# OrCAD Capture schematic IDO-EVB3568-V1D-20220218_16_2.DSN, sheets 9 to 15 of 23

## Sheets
9 P11. VO-HDMI2.0 TX: size A4; note: VO-HDMI2.0 TX
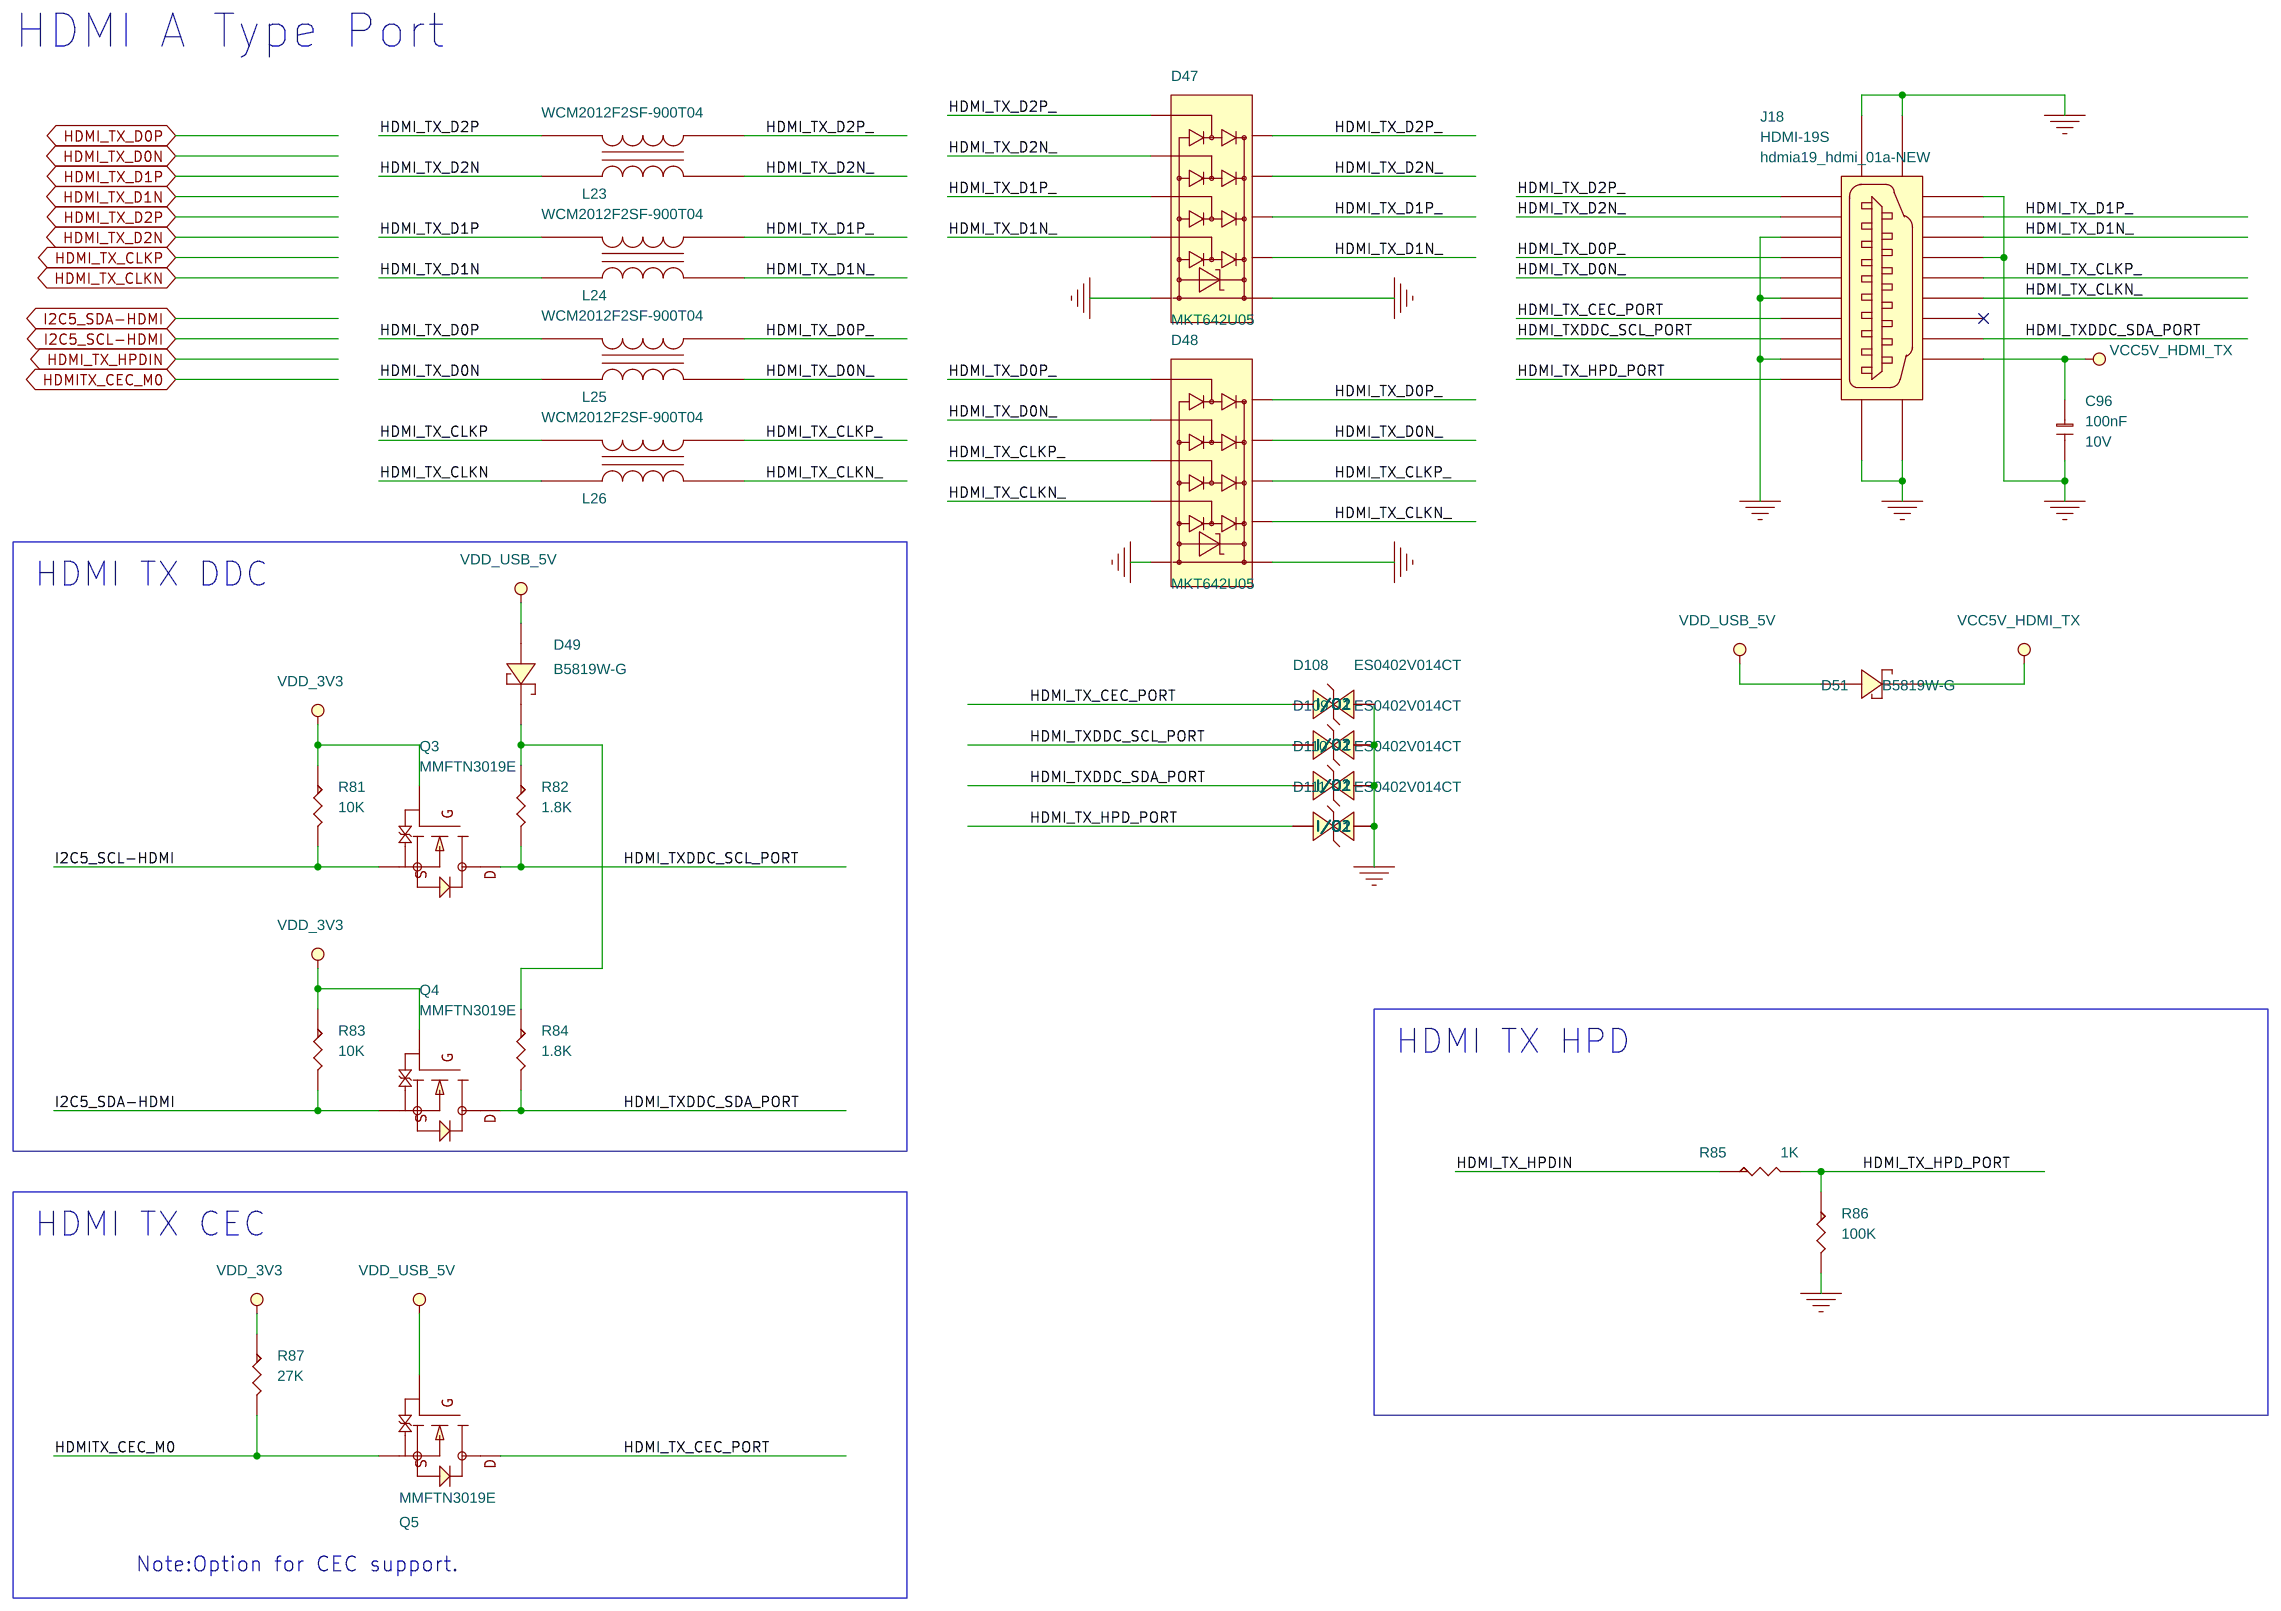
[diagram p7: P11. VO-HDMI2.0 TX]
10 P12. VO-LCM_eDP TX: size A4; note: VO-LCM_eDP TX
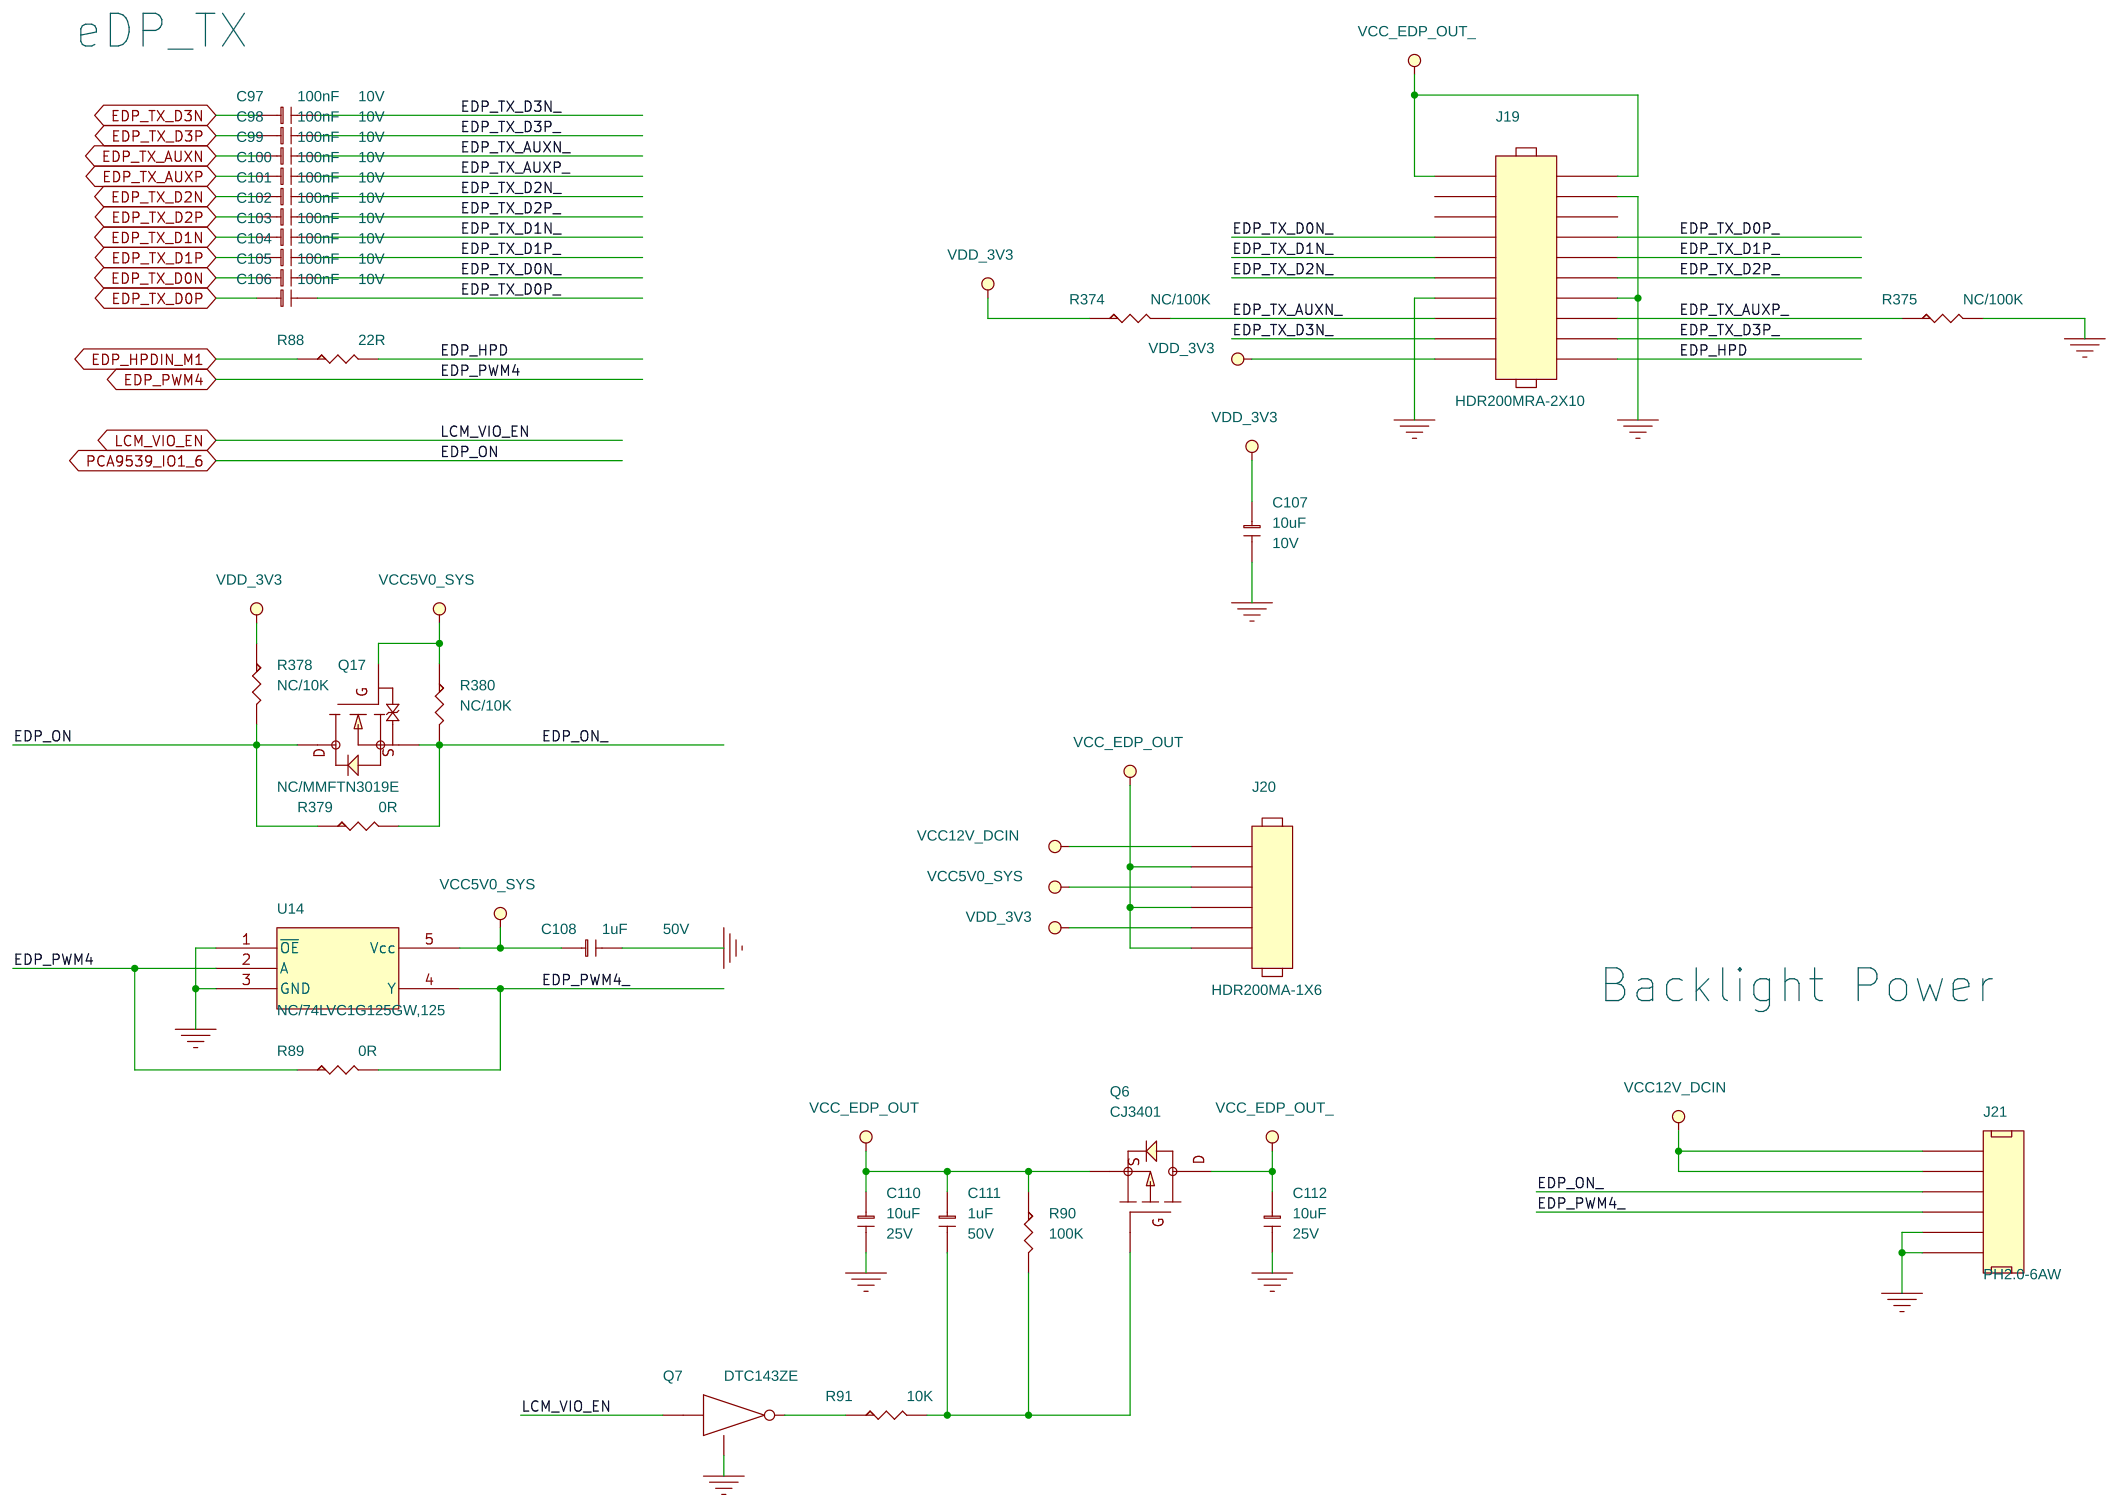
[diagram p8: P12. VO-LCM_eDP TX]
11 P13. VO-LCM_MIPI_DSI_TX0: size A4; note: VO-LCM_MIPI_DSI_TX0
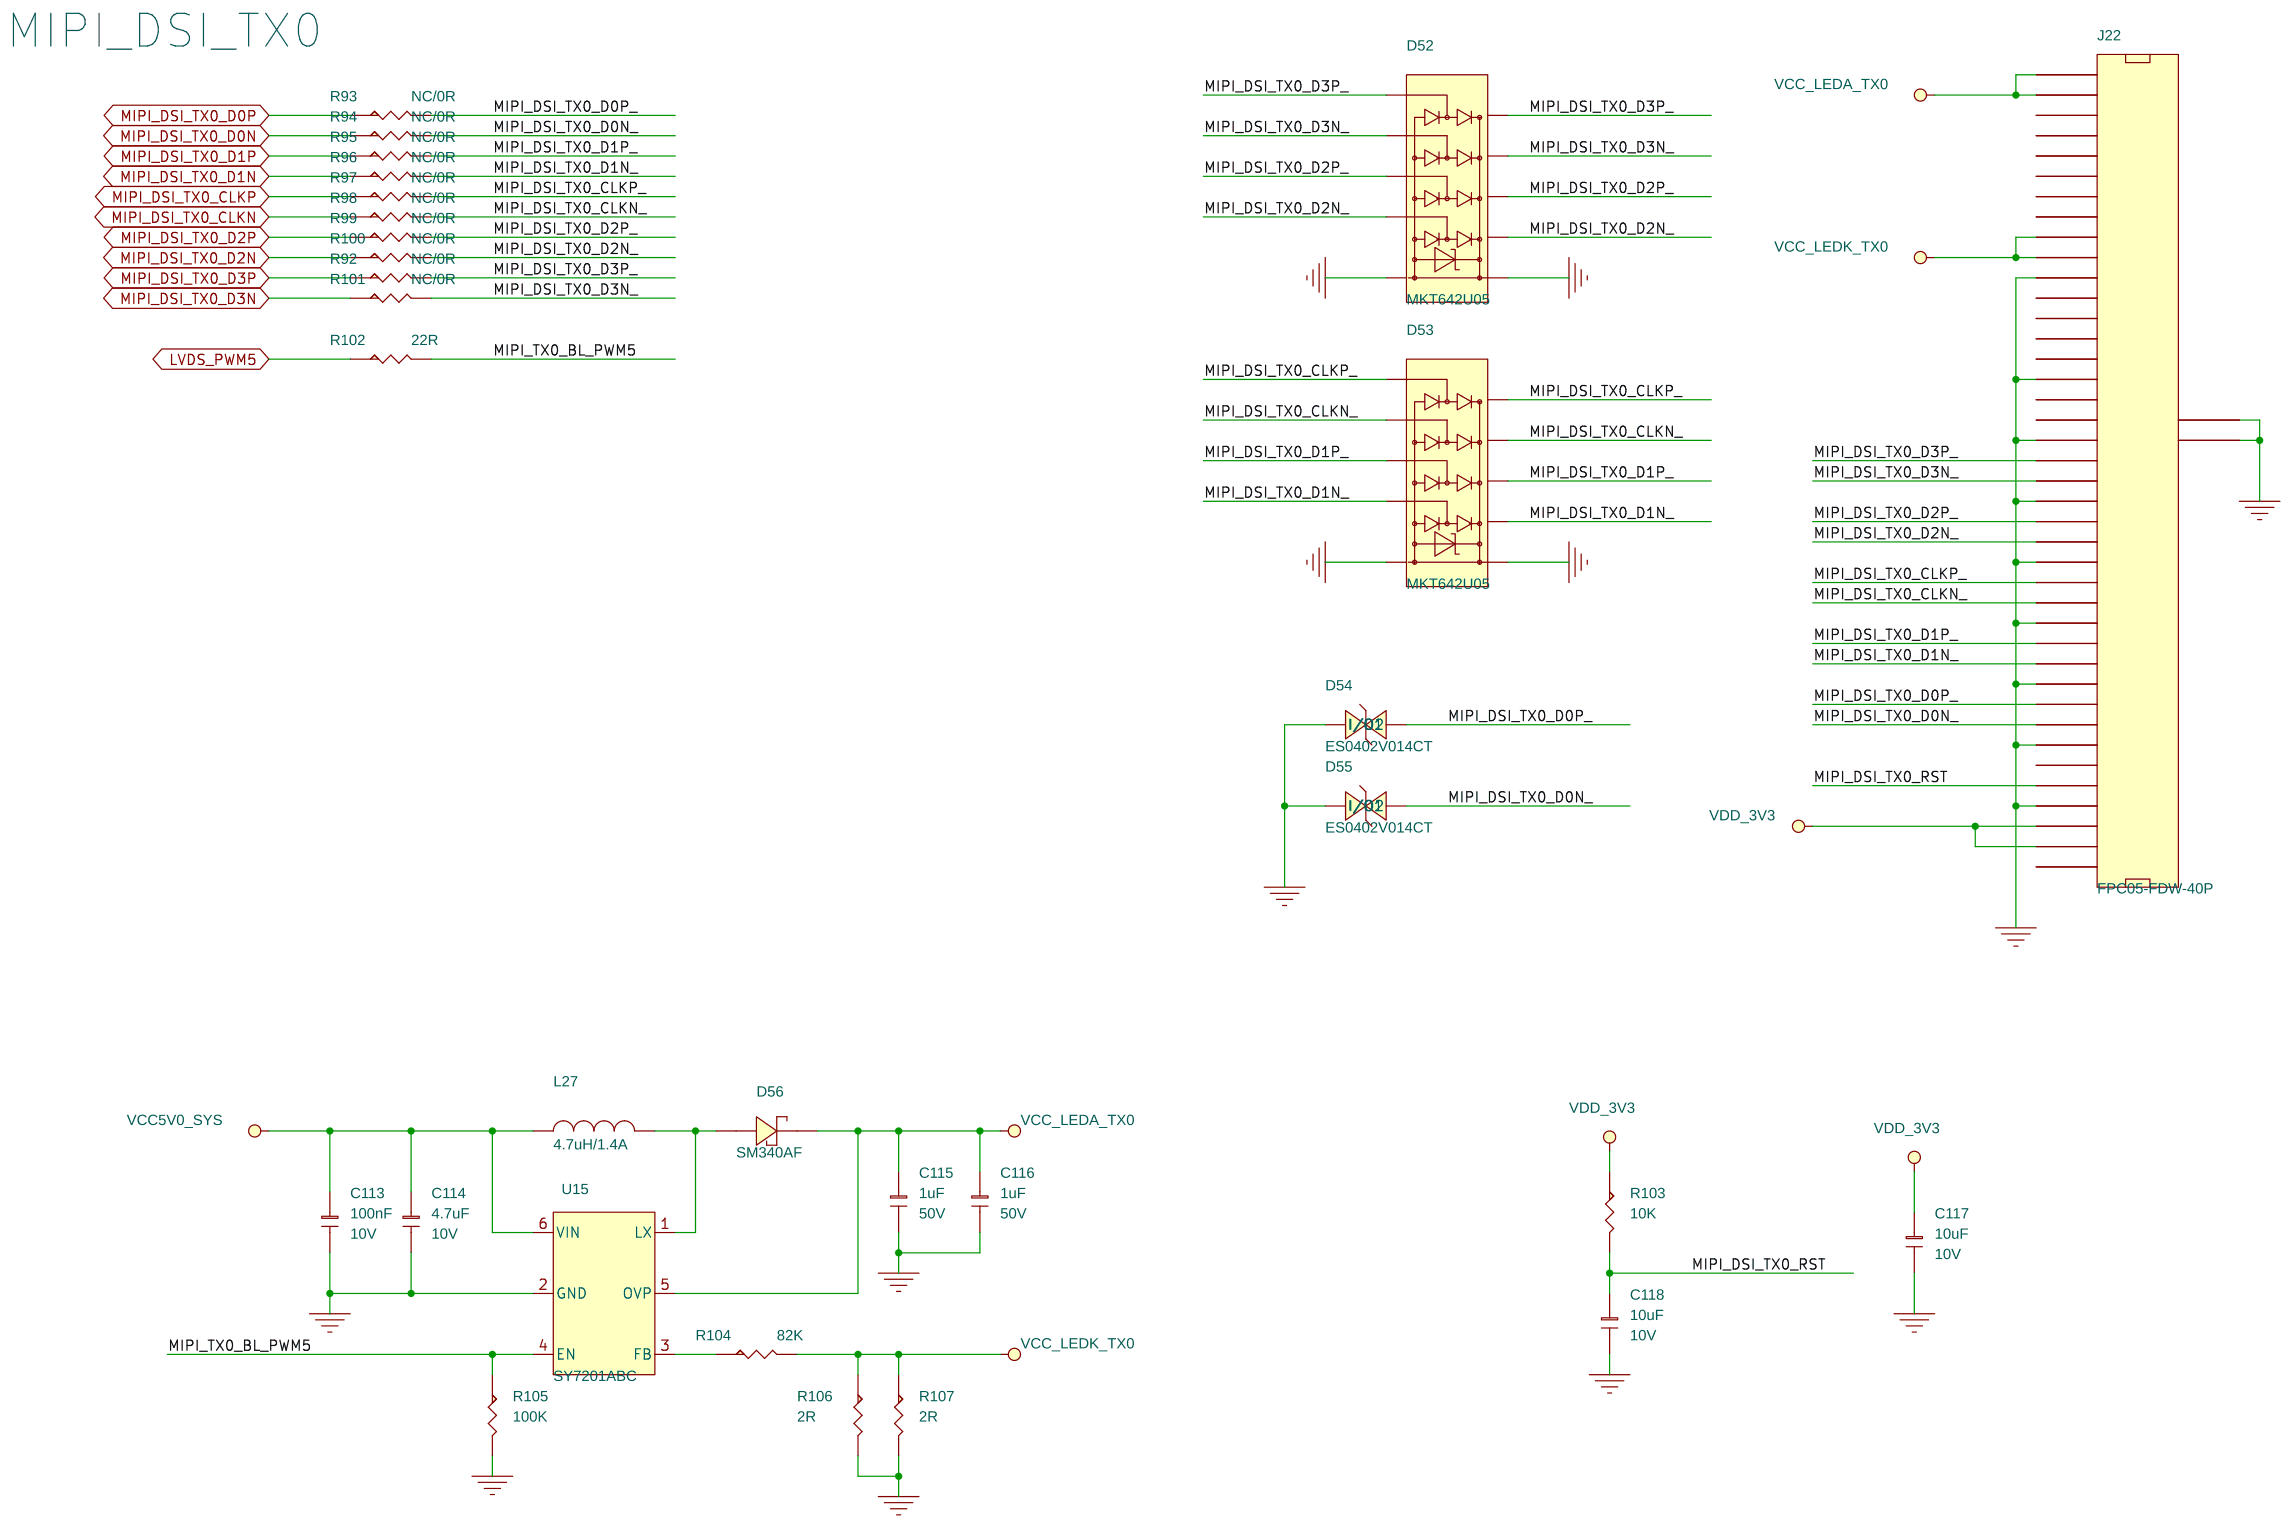
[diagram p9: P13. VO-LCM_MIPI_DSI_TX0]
12 P14. VO-LCM_MIPI_DSI_TX1: size A4; note: VO-LCM_MIPI_DSI_TX1
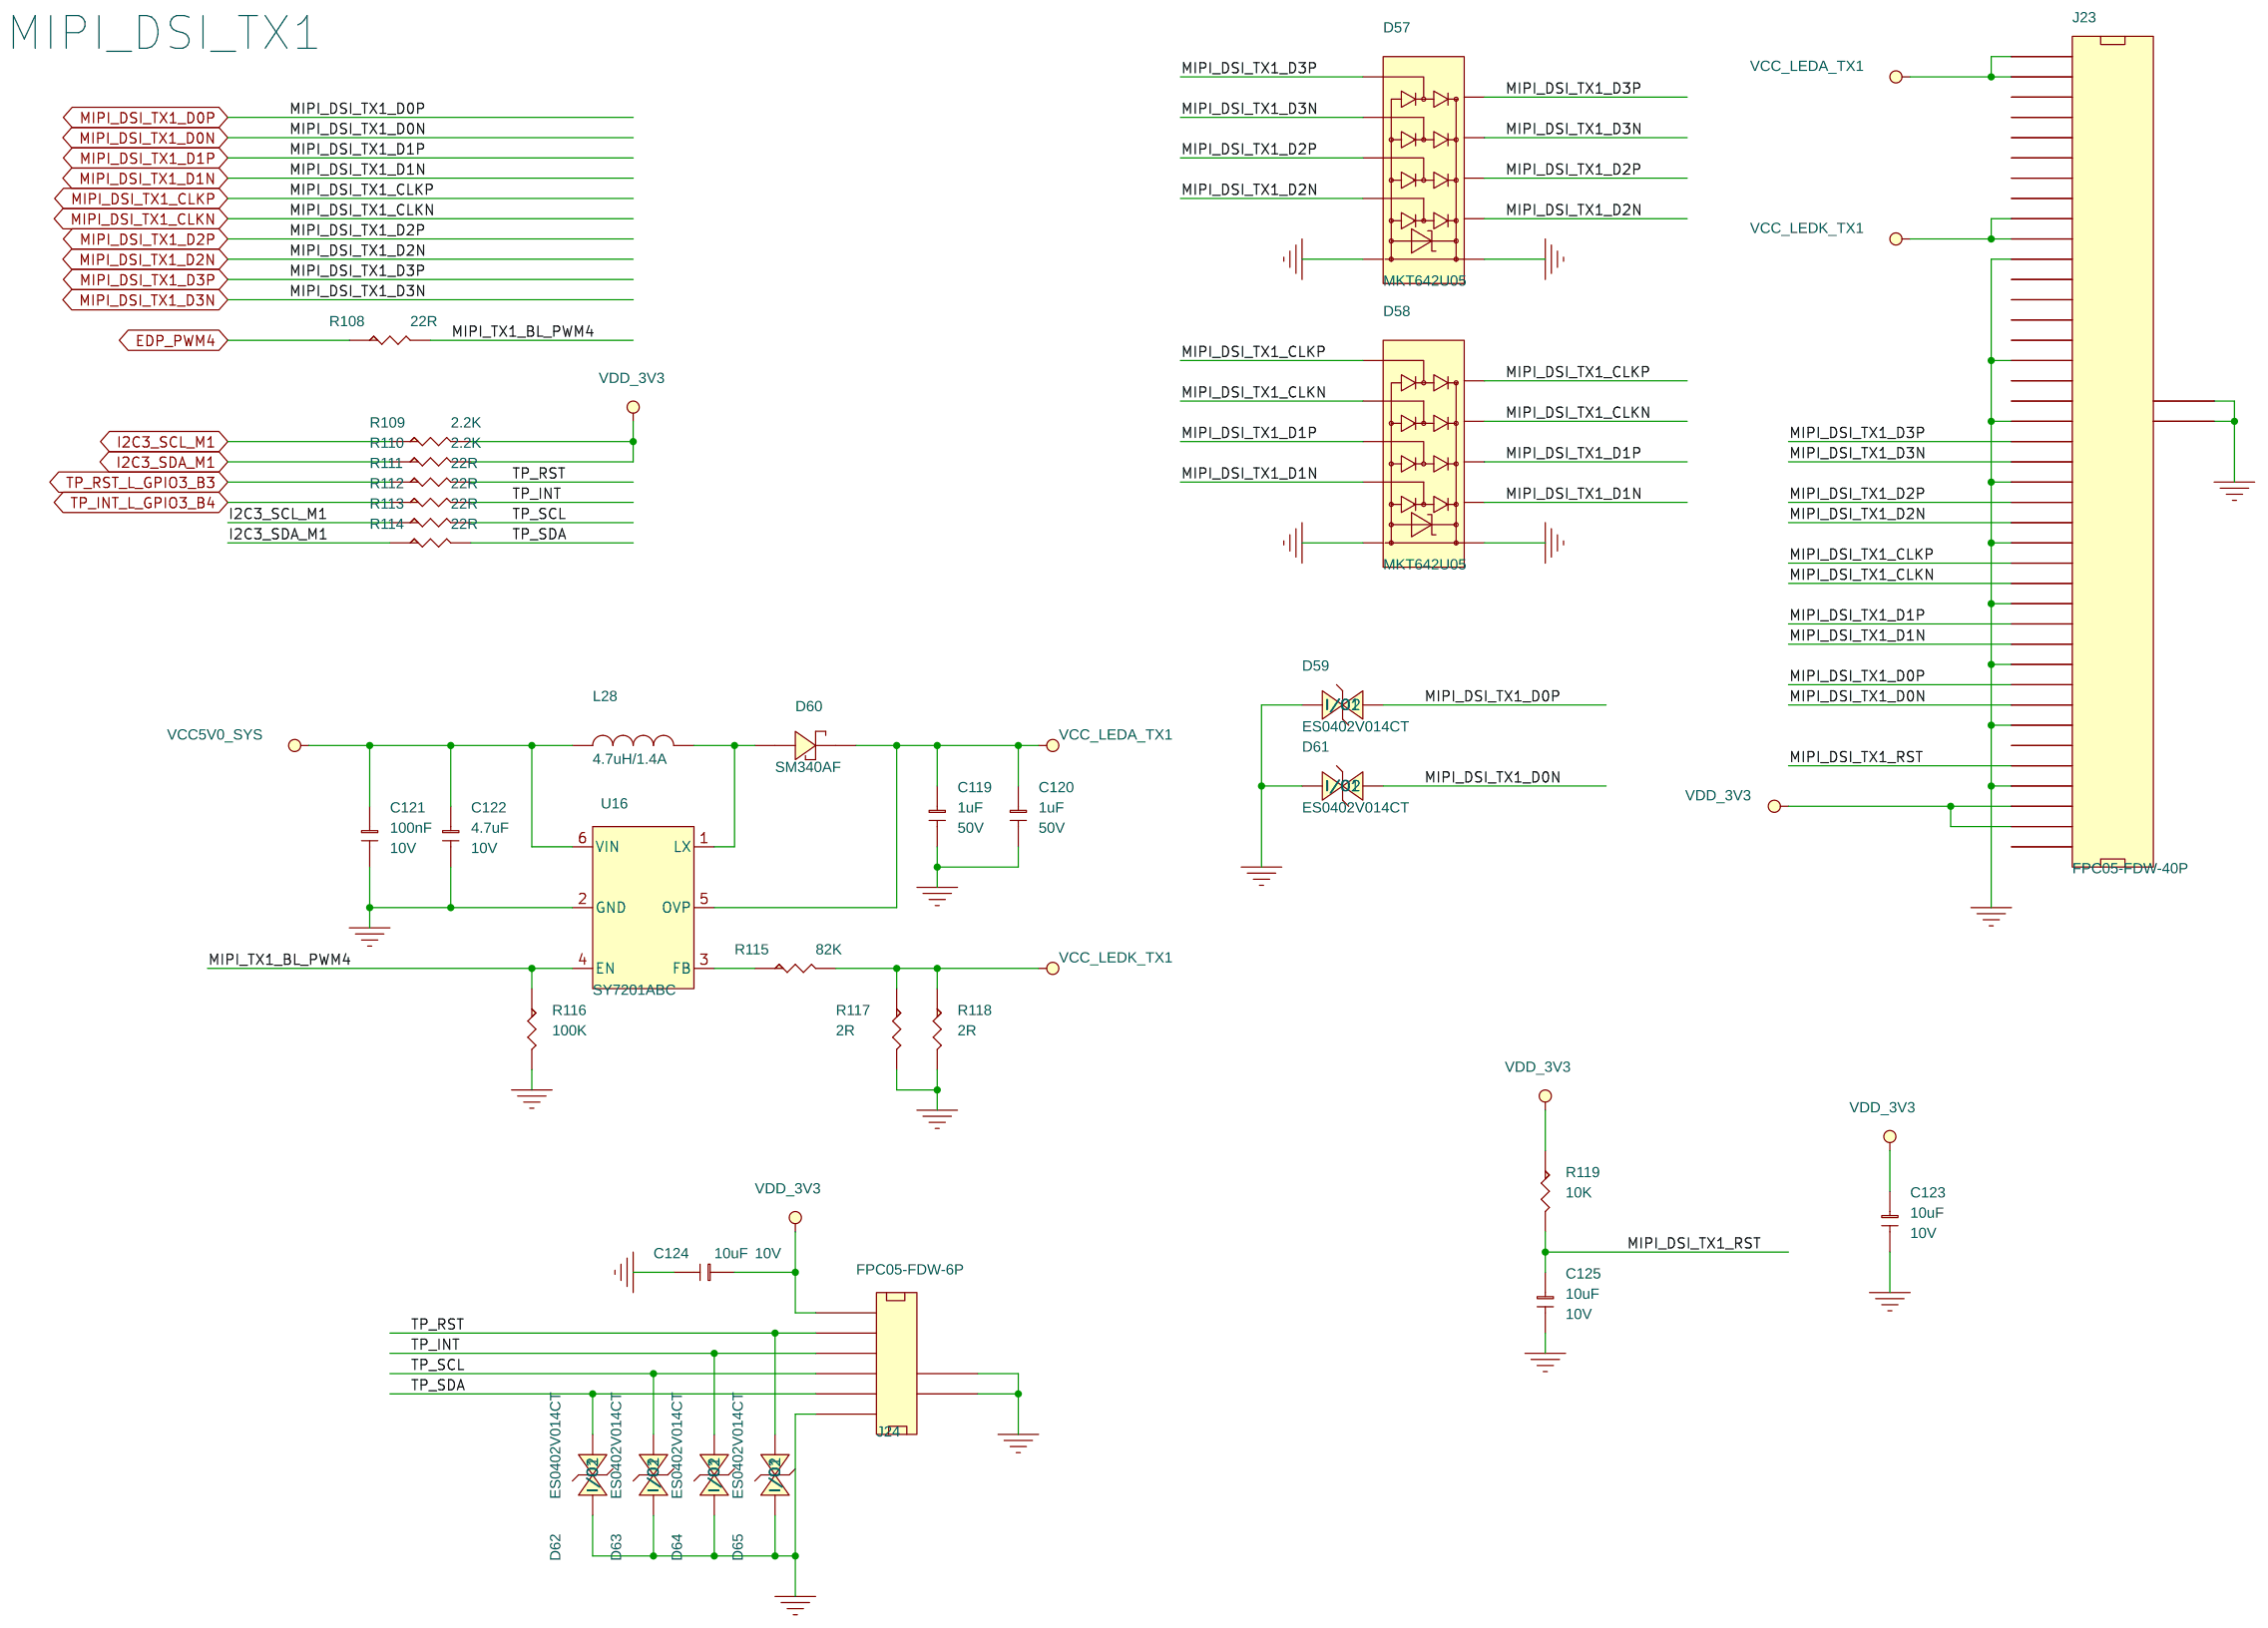
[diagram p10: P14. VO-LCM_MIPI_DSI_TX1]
13 P15. VO-GM8775C-LVDS: size A3; note: VO-GM8775C-LVDS
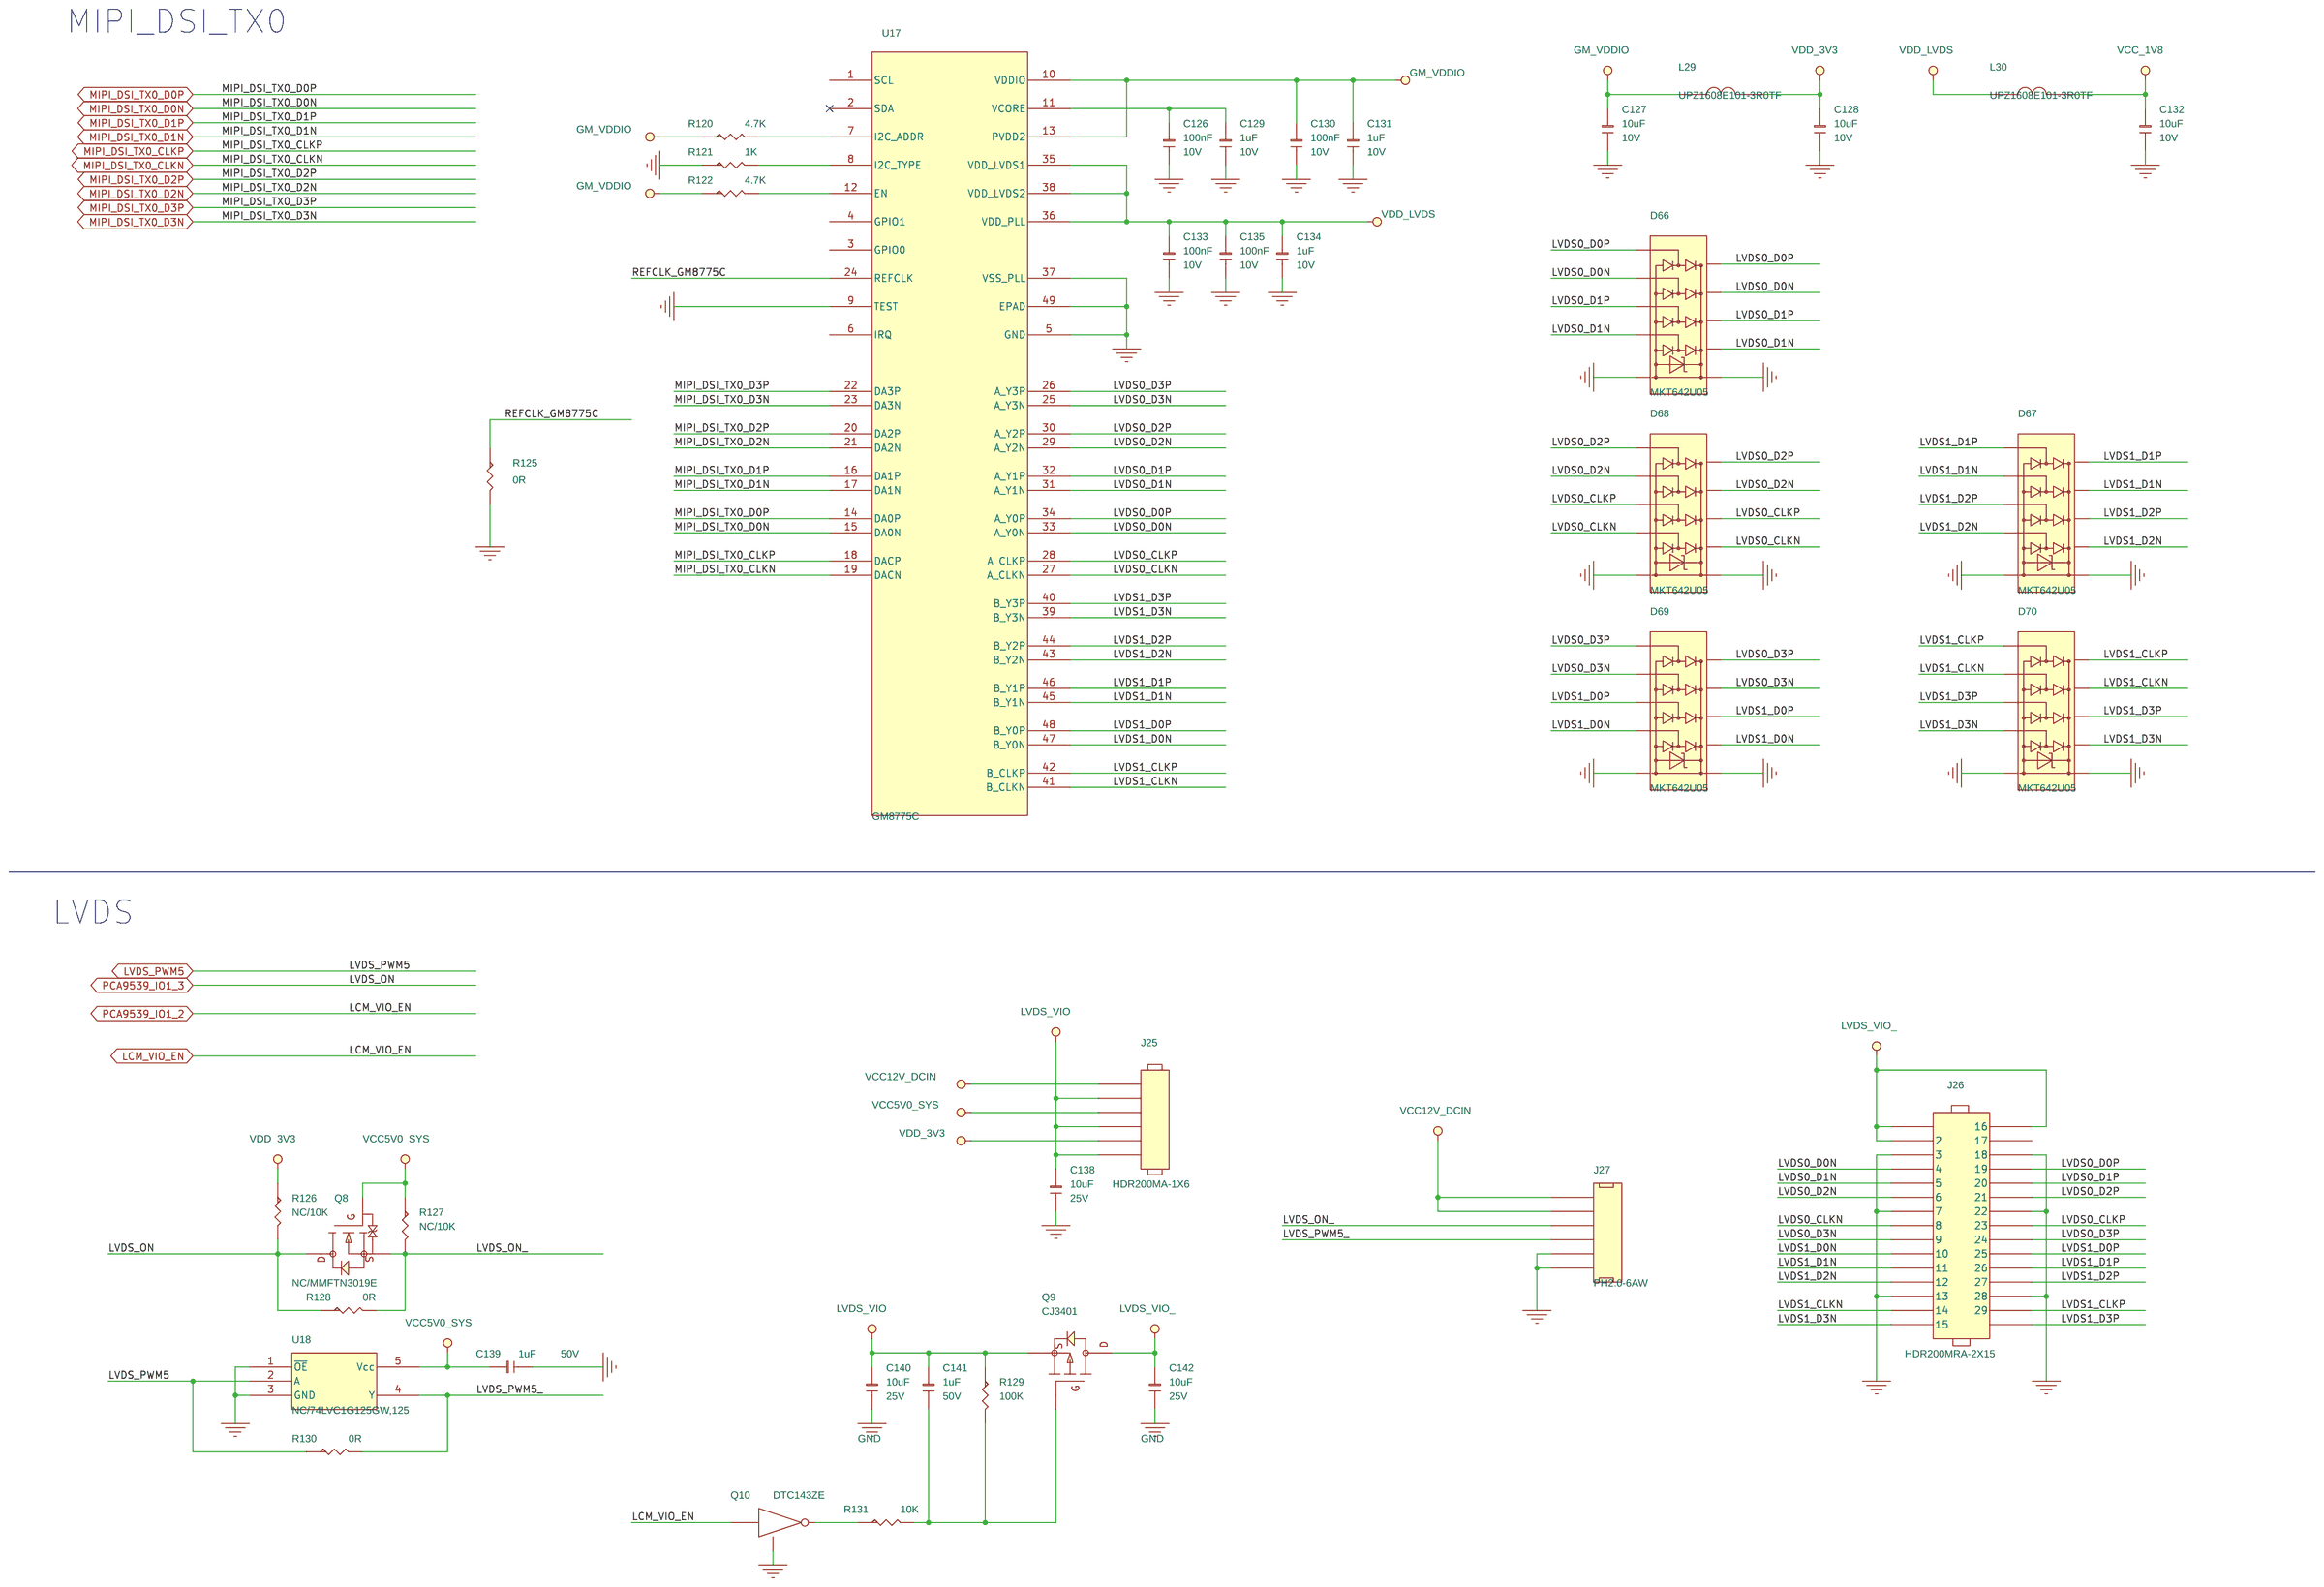
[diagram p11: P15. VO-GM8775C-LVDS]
14 P16. VI-OV5648: size A4; note: VI-OV5648
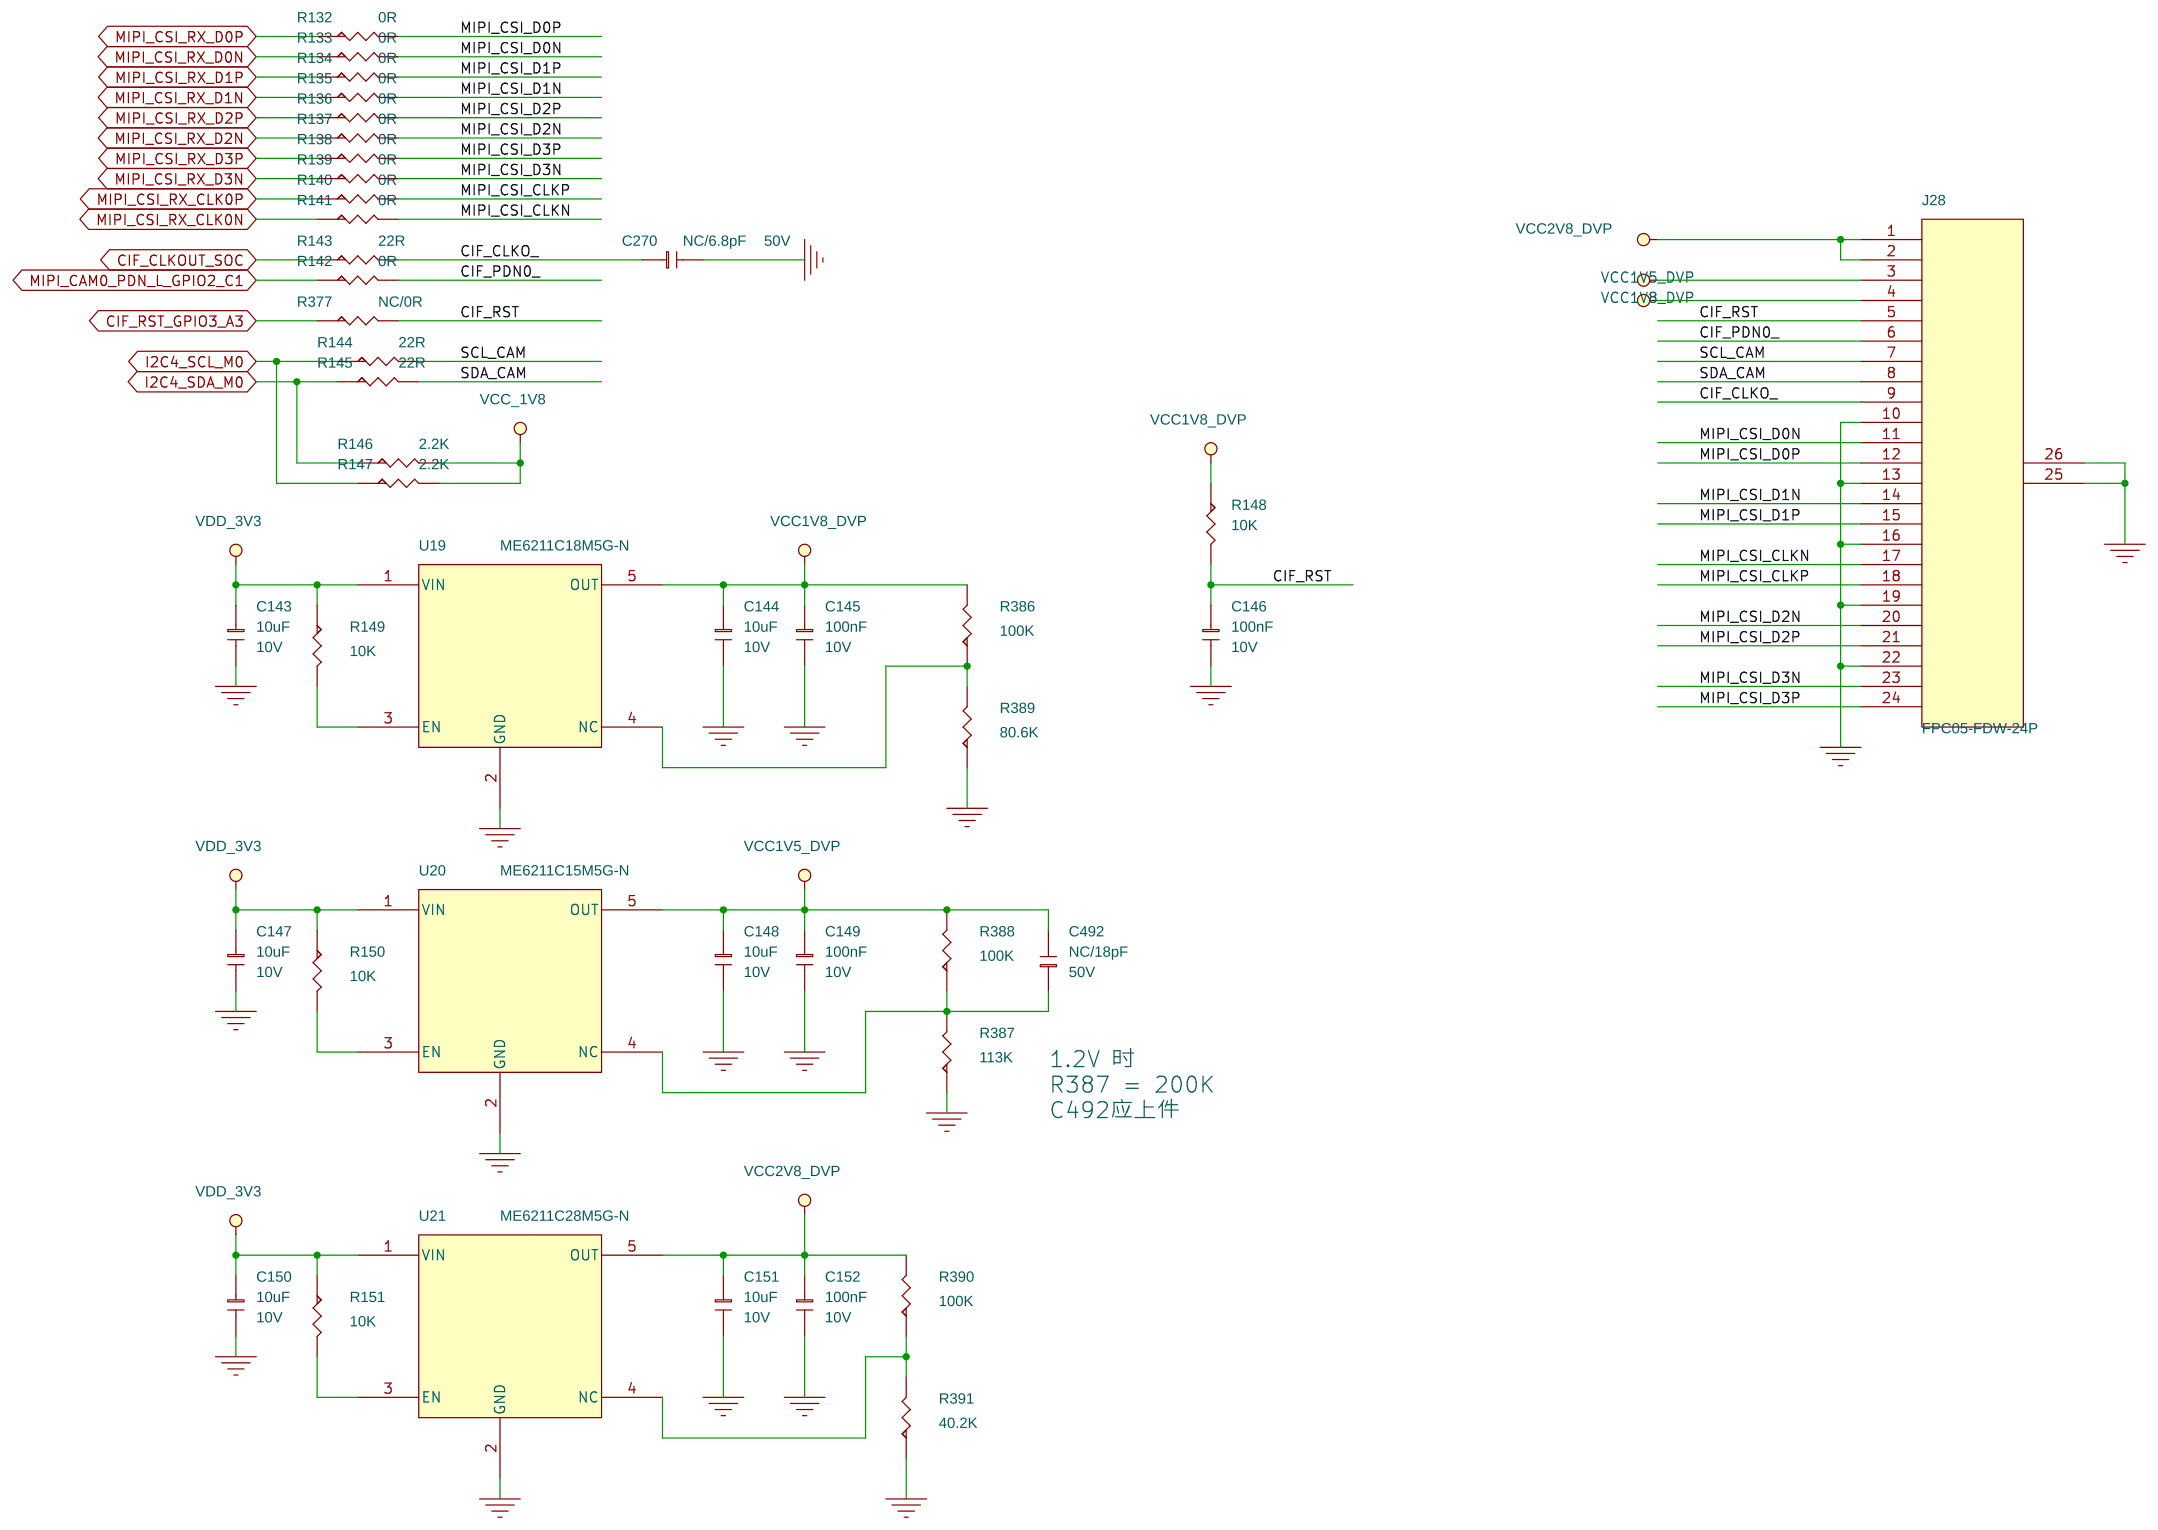
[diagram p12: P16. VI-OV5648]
15 P18. Ethernet-GEPHY_RGMII0: size A2; note: Ethernet-GEPHY_RGMII0
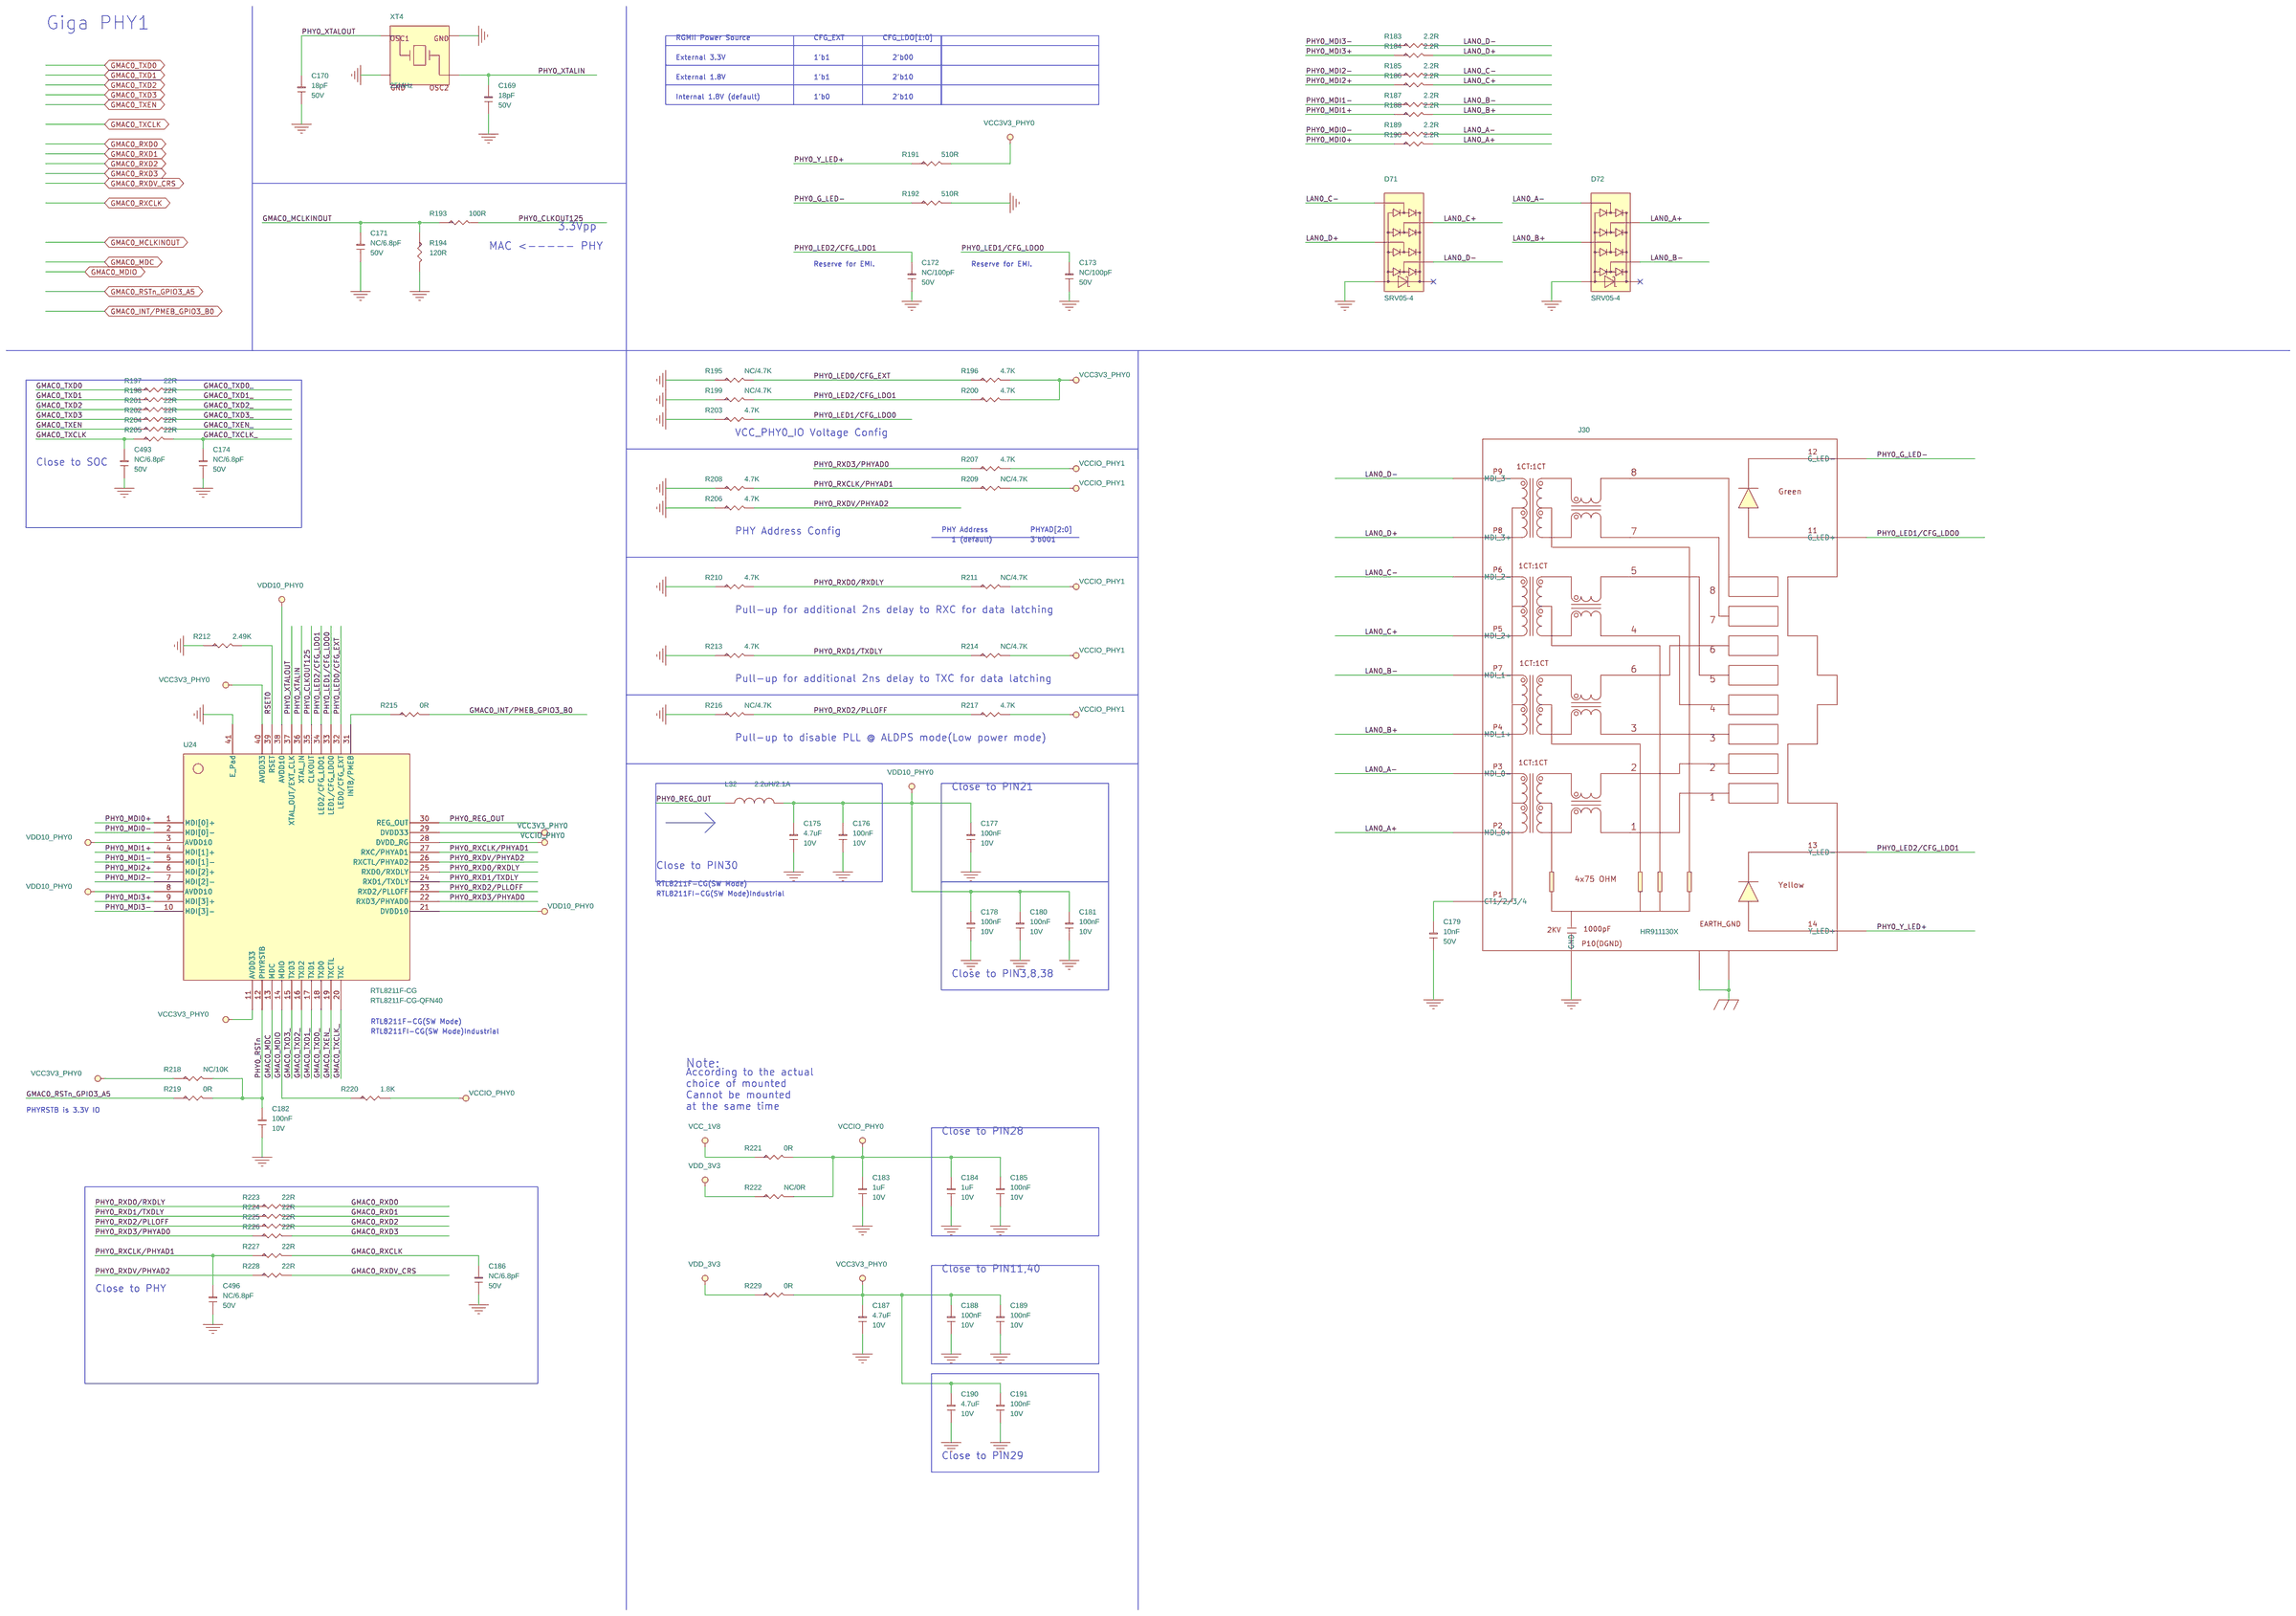
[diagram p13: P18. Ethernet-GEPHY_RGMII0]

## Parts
sheet P11. VO-HDMI2.0 TX
C96  100nF  [C0402L]
D47  MKT642U05  [ESD-DFN2510A-10]
D48  MKT642U05  [ESD-DFN2510A-10]
D49  B5819W-G  [SOD123]
D51  B5819W-G  [SOD123]
D108  ES0402V014CT  [V0402]
D109  ES0402V014CT  [V0402]
D110  ES0402V014CT  [V0402]
D111  ES0402V014CT  [V0402]
J18  HDMI-19S  [hdmia19_hdmi_01a-NEW]
L23  WCM2012F2SF-900T04  [CMLS-ACM2012]
L24  WCM2012F2SF-900T04  [CMLS-ACM2012]
L25  WCM2012F2SF-900T04  [CMLS-ACM2012]
L26  WCM2012F2SF-900T04  [CMLS-ACM2012]
Q3  MMFTN3019E  [SOT523]
Q4  MMFTN3019E  [SOT523]
Q5  MMFTN3019E  [SOT523]
R81  10K  [R0402L]
R82  1.8K  [R0402L]
R83  10K  [R0402L]
R84  1.8K  [R0402L]
R85  1K  [R0402L]
R86  100K  [R0402L]
R87  27K  [R0402L]
sheet P12. VO-LCM_eDP TX
C97  100nF  [C0402L]
C98  100nF  [C0402L]
C99  100nF  [C0402L]
C100  100nF  [C0402L]
C101  100nF  [C0402L]
C102  100nF  [C0402L]
C103  100nF  [C0402L]
C104  100nF  [C0402L]
C105  100nF  [C0402L]
C106  100nF  [C0402L]
C107  10uF  [C0603L]
C108  1uF  [C0603L]
C110  10uF  [C0805L]
C111  1uF  [C0603L]
C112  10uF  [C0805L]
J19  HDR200MRA-2X10  [HDR200MRA-2X10]
J20  HDR200MA-1X6  [HDR200MA-1X6]
J21  PH2.0-6AW  [PH200-6AW]
Q6  CJ3401  [SOT23]
Q7  DTC143ZE  [SOT523]
Q17  NC/MMFTN3019E  [SOT523]
R88  22R  [R0402L]
R89  0R  [R0402L]
R90  100K  [R0402L]
R91  10K  [R0402L]
R374  NC/100K  [R0402L]
R375  NC/100K  [R0402L]
R378  NC/10K  [R0402L]
R379  0R  [R0402L]
R380  NC/10K  [R0402L]
U14  NC/74LVC1G125GW,125  [SOT353]
sheet P13. VO-LCM_MIPI_DSI_TX0
C113  100nF  [C0402L]
C114  4.7uF  [C0402L]
C115  1uF  [C0603L]
C116  1uF  [C0603L]
C117  10uF  [C0603L]
C118  10uF  [C0603L]
D52  MKT642U05  [ESD-DFN2510A-10]
D53  MKT642U05  [ESD-DFN2510A-10]
D54  ES0402V014CT  [V0402]
D55  ES0402V014CT  [V0402]
D56  SM340AF  [SMAF]
J22  FPC05-FDW-40P  [FPC05-FDW-40P]
L27  4.7uH/1.4A  [L2520]
R92  NC/0R  [R0402L]
R93  NC/0R  [R0402L]
R94  NC/0R  [R0402L]
R95  NC/0R  [R0402L]
R96  NC/0R  [R0402L]
R97  NC/0R  [R0402L]
R98  NC/0R  [R0402L]
R99  NC/0R  [R0402L]
R100  NC/0R  [R0402L]
R101  NC/0R  [R0402L]
R102  22R  [R0402L]
R103  10K  [R0402L]
R104  82K  [R0402L]
R105  100K  [R0402L]
R106  2R  [R0805L]
R107  2R  [R0805L]
U15  SY7201ABC  [SOT23-6]
sheet P14. VO-LCM_MIPI_DSI_TX1
C119  1uF  [C0603L]
C120  1uF  [C0603L]
C121  100nF  [C0402L]
C122  4.7uF  [C0402L]
C123  10uF  [C0603L]
C124  10uF  [C0603L]
C125  10uF  [C0603L]
D57  MKT642U05  [ESD-DFN2510A-10]
D58  MKT642U05  [ESD-DFN2510A-10]
D59  ES0402V014CT  [V0402]
D60  SM340AF  [SMAF]
D61  ES0402V014CT  [V0402]
D62  ES0402V014CT  [V0402]
D63  ES0402V014CT  [V0402]
D64  ES0402V014CT  [V0402]
D65  ES0402V014CT  [V0402]
J23  FPC05-FDW-40P  [FPC05-FDW-40P]
J24  FPC05-FDW-6P  [FPC05-FDW-6P]
L28  4.7uH/1.4A  [L2520]
R108  22R  [R0402L]
R109  2.2K  [R0402L]
R110  2.2K  [R0402L]
R111  22R  [R0402L]
R112  22R  [R0402L]
R113  22R  [R0402L]
R114  22R  [R0402L]
R115  82K  [R0402L]
R116  100K  [R0402L]
R117  2R  [R0805L]
R118  2R  [R0805L]
R119  10K  [R0402L]
U16  SY7201ABC  [SOT23-6]
sheet P15. VO-GM8775C-LVDS
C126  100nF  [C0402L]
C127  10uF  [C0603L]
C128  10uF  [C0603L]
C129  1uF  [C0402L]
C130  100nF  [C0402L]
C131  1uF  [C0402L]
C132  10uF  [C0603L]
C133  100nF  [C0402L]
C134  1uF  [C0402L]
C135  100nF  [C0402L]
C138  10uF  [C0805L]
C139  1uF  [C0603L]
C140  10uF  [C0805L]
C141  1uF  [C0603L]
C142  10uF  [C0805L]
D66  MKT642U05  [ESD-DFN2510A-10]
D67  MKT642U05  [ESD-DFN2510A-10]
D68  MKT642U05  [ESD-DFN2510A-10]
D69  MKT642U05  [ESD-DFN2510A-10]
D70  MKT642U05  [ESD-DFN2510A-10]
J25  HDR200MA-1X6  [HDR200MA-1X6]
J26  HDR200MRA-2X15  [HDR200MRA-2X15]
J27  PH2.0-6AW  [PH200-6AW]
L29  UPZ1608E101-3R0TF  [L0603]
L30  UPZ1608E101-3R0TF  [L0603]
Q8  NC/MMFTN3019E  [SOT523]
Q9  CJ3401  [SOT23]
Q10  DTC143ZE  [SOT523]
R120  4.7K  [R0402L]
R121  1K  [R0402L]
R122  4.7K  [R0402L]
R125  0R  [R0402L]
R126  NC/10K  [R0402L]
R127  NC/10K  [R0402L]
R128  0R  [R0402L]
R129  100K  [R0402L]
R130  0R  [R0402L]
R131  10K  [R0402L]
U17  GM8775C  [qfn50p700x700x100-49an]
U18  NC/74LVC1G125GW,125  [SOT353]
sheet P16. VI-OV5648
C143  10uF  [C0603L]
C144  10uF  [C0603L]
C145  100nF  [C0402L]
C146  100nF  [C0402L]
C147  10uF  [C0603L]
C148  10uF  [C0603L]
C149  100nF  [C0402L]
C150  10uF  [C0603L]
C151  10uF  [C0603L]
C152  100nF  [C0402L]
C270  NC/6.8pF  [C0402L]
C492  NC/18pF  [C0402L]
J28  FPC05-FDW-24P  [FPC05-ZDW-24P]
R132  0R  [R0402L]
R133  0R  [R0402L]
R134  0R  [R0402L]
R135  0R  [R0402L]
R136  0R  [R0402L]
R137  0R  [R0402L]
R138  0R  [R0402L]
R139  0R  [R0402L]
R140  0R  [R0402L]
R141  0R  [R0402L]
R142  0R  [R0402L]
R143  22R  [R0402L]
R144  22R  [R0402L]
R145  22R  [R0402L]
R146  2.2K  [R0402L]
R147  2.2K  [R0402L]
R148  10K  [R0402L]
R149  10K  [R0402L]
R150  10K  [R0402L]
R151  10K  [R0402L]
R377  NC/0R  [R0402L]
R386  100K  [R0402L]
R387  113K  [R0402L]
R388  100K  [R0402L]
R389  80.6K  [R0402L]
R390  100K  [R0402L]
R391  40.2K  [R0402L]
U19  ME6211C18M5G-N  [SOT23-5]
U20  ME6211C15M5G-N  [SOT23-5]
U21  ME6211C28M5G-N  [SOT23-5]
sheet P18. Ethernet-GEPHY_RGMII0
C169  18pF  [C0402L]
C170  18pF  [C0402L]
C171  NC/6.8pF  [C0402L]
C172  NC/100pF  [C0402L]
C173  NC/100pF  [C0402L]
C174  NC/6.8pF  [C0402L]
C175  4.7uF  [C0402L]
C176  100nF  [C0402L]
C177  100nF  [C0402L]
C178  100nF  [C0402L]
C179  10nF  [C0402L]
C180  100nF  [C0402L]
C181  100nF  [C0402L]
C182  100nF  [C0402L]
C183  1uF  [C0402L]
C184  1uF  [C0402L]
C185  100nF  [C0402L]
C186  NC/6.8pF  [C0402L]
C187  4.7uF  [C0402L]
C188  100nF  [C0402L]
C189  100nF  [C0402L]
C190  4.7uF  [C0402L]
C191  100nF  [C0402L]
C493  NC/6.8pF  [C0402L]
C496  NC/6.8pF  [C0402L]
D71  SRV05-4  [SOT23-6]
D72  SRV05-4  [SOT23-6]
J30  HR911130X  [HR911130X]
L32  2.2uH/2.1A  [L2520]
R183  2.2R  [R0402L]
R184  2.2R  [R0402L]
R185  2.2R  [R0402L]
R186  2.2R  [R0402L]
R187  2.2R  [R0402L]
R188  2.2R  [R0402L]
R189  2.2R  [R0402L]
R190  2.2R  [R0402L]
R191  510R  [R0402L]
R192  510R  [R0402L]
R193  100R  [R0402L]
R194  120R  [R0402L]
R195  NC/4.7K  [R0402L]
R196  4.7K  [R0402L]
R197  22R  [R0402L]
R198  22R  [R0402L]
R199  NC/4.7K  [R0402L]
R200  4.7K  [R0402L]
R201  22R  [R0402L]
R202  22R  [R0402L]
R203  4.7K  [R0402L]
R204  22R  [R0402L]
R205  22R  [R0402L]
R206  4.7K  [R0402L]
R207  4.7K  [R0402L]
R208  4.7K  [R0402L]
R209  NC/4.7K  [R0402L]
R210  4.7K  [R0402L]
R211  NC/4.7K  [R0402L]
R212  2.49K  [R0402L]
R213  4.7K  [R0402L]
R214  NC/4.7K  [R0402L]
R215  0R  [R0402L]
R216  NC/4.7K  [R0402L]
R217  4.7K  [R0402L]
R218  NC/10K  [R0402L]
R219  0R  [R0402L]
R220  1.8K  [R0402L]
R221  0R  [R0402L]
R222  NC/0R  [R0402L]
R223  22R  [R0402L]
R224  22R  [R0402L]
R225  22R  [R0402L]
R226  22R  [R0402L]
R227  22R  [R0402L]
R228  22R  [R0402L]
R229  0R  [R0402L]
U24  RTL8211F-CG  [RTL8211F-CG-QFN40]
XT4  25MHz  [xtal_32x25_4p]

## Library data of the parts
C96-C106 C113 C121 C126 C130 C133 C135 C145 C146 C149 C152 C176-C178 C180-C182 C185 C188 C189 C191 = C-0402: DSC1: ±10%; DSC2: 10V; DSC3: X7R; ID: 60; Manufacture: 三星|国巨|村田; Part Name: 贴片电容; Part Number: C020102120060; Price: 0.01
D47 D48 D52 D53 D57 D58 D66-D70 = DI-ESD-MKT642U05: DSC2: Vdc=5V; DSC3: Vbr=6V; DSC4: Vc=16V; DSC5: Cj=0.35pF; ID: 8; Manufacture: 米客方德; Part Name: ESD; Part Number: C040502250008; Price: 0.15; Solder: 推荐
D49 D51 = DI-XI-S: DSC1: VR=40V; DSC2: IF=1A; DSC3: VF=600mV/1A; DSC4: IR=1mA; ID: 5; Manufacture: 长电; Part Name: 肖特基二级管; Part Number: C040202220005; Price: 0.13
D54 D55 D59 D61-D65 D108-D111 = DI-ESD: DSC1: 双向; DSC2: Vdc=14V; DSC3: Vbr=300V; DSC4: Vc=30V; DSC5: Cj=0.25pF; ERP Number: 1010800023; ID: 2; Manufacture: AEM; Part Name: ESD; Part Number: C040502250002; Price: 0.06
J18 = J-HDMI-19P: DSC1: HDMI 19P母座SMT铜壳四脚 黑胶LCP 耐高温; DSC2: 15*11.8*6mm; DSC3: 贴片; ID: 7; Part Name: HDMI座; Part Number: J050302920001
L23-L26 = L-CMLS-ACM2012: DSC1: 90uH@100kHz; DSC2: 90Ω@100MHz; DSC3: 400mA; DSC4: DCR=300mΩ; DSC5: -40℃ ~ +125℃; DSC6: SMD_4P,2x1.2mm; ERP Number: 1010200196; ID: 1; Manufacture: 台庆; Part Name: 信号共模电感; Part Number: C060402360001; Price: 0.13
Q3-Q5 Q8 Q17 = N-MOS-Q: DSC1: Vds=30V; DSC2: Id=100mA; DSC3: Vgs(th)=1.5V; DSC4: Vgs=±20V; DSC5: pd=150mW; ERP Number: 1010800011; ID: 4; Manufacture: 先科; Part Name: N-MOS; Part Number: C030202190004; Price: 0.1
R81 R83 R91 R103 R119 R126 R127 R131 R148-R151 R218 R378 R380 = R-0402: DSC1: ±1%; DSC2: 1/16W; ERP Number: 1010200140; ID: 856; Part Name: 贴片电阻; Part Number: C011002080856; Price: 0.01
R82 R84 R220 = R-0402: DSC1: ±1%; DSC2: 1/16W; ID: 769; Part Name: 贴片电阻; Part Number: C011002080769; Price: 0.01
R85 R121 = R-0402: DSC1: ±1%; DSC2: 1/16W; ERP Number: 1010200113; ID: 742; Part Name: 贴片电阻; Part Number: C011002080742; Price: 0.01
R86 R90 R105 R116 R129 R374 R375 = R-0402: DSC1: ±1%; DSC2: 1/16W; ERP Number: 1010200137; ID: 976; Part Name: 贴片电阻; Part Number: C011002080976; Price: 0.01
R87 = R-0402: DSC1: ±1%; DSC2: 1/16W; ID: 904; Part Name: 贴片电阻; Part Number: C011002080904; Price: 0.01
C107 C117 C118 C123-C125 C127 C128 C132 C143 C144 C147 C148 C150 C151 = C-0603: DSC1: ±20%; DSC2: 10V; DSC3: X5R; ERP Number: 1010200076; ID: 71; Manufacture: 三星|国巨|村田; Part Name: 贴片电容; Part Number: C020102120071; Price: 0.05
C108 C111 C115 C116 C119 C120 C139 C141 = C-0603: DSC1: ±10%; DSC2: 50V; DSC3: X5R; ERP Number: 1010200142; ID: 69; Manufacture: 三星|国巨|村田; Part Name: 贴片电容; Part Number: C020102120069; Price: 0.04
C110 C112 C138 C140 C142 = C-0805: DSC1: ±10%; DSC2: 25V; DSC3: X5R; ERP Number: 1010200144; ID: 74; Manufacture: 三星|国巨|村田; Part Name: 贴片电容; Part Number: C020102120074; Price: 0.09
J19 = J-HDR-D-20: DSC1: 双排单塑; DSC2: 2x10; DSC3: 2mm脚距; DSC4: 通孔弯针; DSC5: 2.8+2(H塑高)+4 mm; DSC6: 黑胶; DSC7: A2005WR-2x10P（CJT); ID: 29; Part Name: 双排针; Part Number: J010102760085
J20 J25 = J-HDR-6: DSC1: 单排单塑; DSC2: 1x6; DSC3: 2mm脚距; DSC4: 通孔直针; DSC5: 针长8.8mm  2.8+2(H塑高)+4 mm; DSC6: 黑胶; ID: 66; Part Name: 单排针; Part Number: J010206123880
J21 J27 = J-H-6P: DSC1: 6p; DSC2: 2.0mm间距; DSC3: 通孔90度弯针; DSC4: 米黄色胶壳 耐高温; DSC5: A2001WR-6P(CJT); ID: 20; Part Name: PH; Part Number: J020302820024
Q6 Q9 = P-MOS: DSC1: Vds=-30V; DSC2: Id=-4.2A; DSC3: Vgs(th)=1.3V; DSC4: Vgs=±12V; DSC5: pd=350mW; ERP Number: 1010800001; ID: 1; Manufacture: 长电; Part Number: C030202190001; Price: 0.17
Q7 Q10 = S-NPN: DSC1: NPN; DSC2: Ic=100mA; DSC3: Vce=50V; DSC4: 150mW; ERP Number: 1010800049; ID: 2; Manufacture: 长电; Part Name: 数字三极管; Part Number: C030302200002; Price: 0.08
R88 R102 R108 R111-R114 R143-R145 R197 R198 R201 R202 R204 R205 R223-R228 = R-0402: DSC1: ±1%; DSC2: 1/16W; ID: 552; Part Name: 贴片电阻; Part Number: C011002080552; Price: 0.01
R89 R92-R101 R125 R128 R130 R132-R142 R215 R219 R221 R222 R229 R377 R379 = R-0402: DSC1: ±1%; DSC2: 1/16W; ID: 413; Part Name: 贴片电阻; Part Number: C011002080413; Price: 0.01
U14 U18 = U-74LVC1G125GW-125: DSC1: 1位 高速缓冲 三态输出 VCC=1.65V-5.5V; DSC2: SOT-353; DSC3: -55℃~+125℃; ERP Number: 1010100128; ID: 5; Manufacture: Nexperia(安世); Part Name: 逻辑缓冲器; Part Number: C080302460001; Price: 0.13
C114 C122 C175 C187 C190 = C-0402: DSC1: ±20%; DSC2: 10V; DSC3: X5R; ID: 67; Manufacture: 三星|国巨|村田; Part Name: 贴片电容; Part Number: C020102120067; Price: 0.04
D56 D60 = DI-XI-S: DSC1: VR=40V; DSC2: IF=3A; DSC3: VF=500mV/3A; ID: 7; Manufacture: 乐山无线电; Part Name: 肖特基二级管; Part Number: C040202220007; Price: 0.15; Solder: 推荐
J22 J23 = J-FPC05-40P: DSC1: 40P; DSC2: 0.5mm间距; DSC3: 下接 翻盖 卧贴; DSC4: H=2mm; DSC5: 镀锡; DSC6: X05A20L40T(星坤); ID: 36; Part Name: FPC座
L27 L28 = L-IND: DSC1: ±20%; DSC2: Isat=1.9A; DSC3: Irms=1.4A; DSC4: 240mΩ; DSC5: 2.5*2.0*1.0mm; DSC6: WPN252010U4R7MT(顺络); Manufacture: 顺络; Part Name: 功率电感; Part Number: C060202340015; Price: 0.2
R104 R115 = R-0402: DSC1: ±1%; DSC2: 1/16W; ID: 965; Part Name: 贴片电阻; Part Number: C011002080965; Price: 0.01
R106 R107 R117 R118 = R-0805: DSC1: ±1%; DSC2: 1/8W; ID: 1,503; Part Name: 贴片电阻; Part Number: C011002081503; Price: 0.01
U15 U16 = U-SY7201A_2: DSC1: Vi=2.5-30V; DSC3: Io=2A; DSC4: Vfb=200mV; DSC5: 0.9; DSC6: 1MHz; DSC7: Boost LED驱动; ERP Number: 1010100053; ID: 24; Manufacture: 矽力杰; Part Name: DCDC; Part Number: C070202410024; Price: 1; Solder: 量产
J24 = J-FPC05-6P: DSC1: 6P; DSC2: 0.5mm间距; DSC3: 下接 翻盖 卧贴; DSC4: H=2mm; DSC5: 镀锡; DSC6: X05A20L06T(星坤); ID: 13; Part Name: FPC座; Part Number: J030102870054
R109 R110 R146 R147 = R-0402: DSC1: ±1%; DSC2: 1/16W; ID: 778; Part Name: 贴片电阻; Part Number: C011002080778; Price: 0.01
C129 C131 C134 C183 C184 = C-0402: DSC1: ±10%; DSC2: 10V; DSC3: X5R; ERP Number: 1010200054; ID: 64; Manufacture: 三星|国巨|村田; Part Name: 贴片电容; Part Number: C020102120064; Price: 0.02
J26 = J-HDR-D-30: DSC1: 双排单塑; DSC2: 2x15; DSC3: 2mm脚距; DSC4: 通孔弯针; DSC5: 2.8+2(H塑高)+4 mm; DSC6: 黑胶; DSC7: A2005WR-2x15P（CJT); ID: 30; Part Name: 双排针; Part Number: J010102760090
L29 L30 = FB-0603: DSC1: 100Ω@100MHz; DSC2: 3A; DSC3: DCR=30mΩ; DSC4: 电源线; ERP Number: 1010200207; ID: 5; Manufacture: 顺络; Part Name: 贴片磁珠; Part Number: C060502370005; Price: 0.03
R120 R122 R195 R196 R199 R200 R203 R206-R211 R213 R214 R216 R217 = R-0402: DSC1: ±1%; DSC2: 1/16W; ERP Number: 1010200445; ID: 818; Part Name: 贴片电阻; Part Number: C011002080818; Price: 0.01
U17 = GM8775C
C171 C174 C186 C270 C493 C496 = C-0402: DSC1: ±0.25PF; DSC2: 50V; DSC3: C0G; ERP Number: 1010200056; ID: 18; Manufacture: 三星|国巨|村田; Part Name: 贴片电容; Part Number: C020102120018; Price: 0.01
C169 C170 C492 = C-0402: DSC1: ±5%; DSC2: 50V; DSC3: C0G; ERP Number: 1010200091; ID: 27; Manufacture: 三星|国巨|村田; Part Name: 贴片电容; Part Number: C020102120027; Price: 0.02
J28 = J-FPC05-24P: DSC1: 24P; DSC2: 0.5mm间距; DSC3: 下接 翻盖 卧贴; DSC4: H=2mm; DSC5: 镀锡; DSC6: X05C2024TZ(星坤); ID: 37; Part Name: FPC座
R386 R388 R390 = R-0402: DSC1: ±1%; DSC2: 1/16W; ERP Number: 1010200137; Part Name: 贴片电阻; Part Number: C011002080976; Price: 0.01
R387 = R-0402: DSC1: ±1%; DSC2: 1/16W; Part Name: 贴片电阻; Part Number: C011002080981; Price: 0.01
R389 = R-0402: DSC1: ±1%; DSC2: 1/16W; ERP Number: 1010200373; Part Name: 贴片电阻; Part Number: C011002080964; Price: 0.01
R391 = R-0402: DSC1: ±1%; DSC2: 1/16W; ERP Number: 1010200179; Part Name: 贴片电阻; Part Number: C011002080926; Price: 0.01
U19 = U-ME6211C18M5G-N: DSC1: Vi=1.5-6.5V; DSC2: Vo=1.8V; DSC3: Io=500mA; DSC4: -62db(1K); DSC5: Iq=30uA; ID: 3; Manufacture: 南京微盟; Part Name: LDO; Part Number: C070102400003; Price: 0.2
U20 = U-ME6211C15M5G-N: DSC1: Vi=1.5-6.5V; DSC2: Vo=1.5V; DSC3: Io=300mA; DSC4: -62db(1K); DSC5: Iq=30uA; ID: 27; Manufacture: 南京微盟; Part Name: LDO; Part Number: C070107223911; Price: 0.2
U21 = U-ME6211C28M5G-N: DSC1: Vi=1.5-6.5V; DSC2: Vo=2.8V; DSC3: Io=500mA; DSC4: -62db(1K); DSC5: Iq=30uA; ID: 18; Manufacture: 南京微盟; Part Name: LDO; Part Number: C070102400018; Price: 0.2
C172 C173 = C-0402: DSC1: ±5%; DSC2: 50V; DSC3: C0G; ERP Number: 1010200152; ID: 40; Manufacture: 三星|国巨|村田; Part Name: 贴片电容; Part Number: C020102120040; Price: 0.01
C179 = C-0402: DSC1: ±10%; DSC2: 50V; DSC3: X7R; ERP Number: 1010200077; ID: 57; Manufacture: 三星|国巨|村田; Part Name: 贴片电容; Part Number: C020102120057; Price: 0.02
D71 D72 = DI-ESD-SRV05-4: DSC1: 单向; DSC2: Vrwm=5V; DSC3: VBR=6V; DSC4: Vc=13V; DSC5: Ipp=3.5A; DSC6: Ppp=45W; DSC7: Cj=0.36pF; ERP Number: 1010800050; ID: 15; Manufacture: 伯恩半导体; Part Name: TVS; Part Number: C040602260015; Price: 0.21; Solder: 量产
J30 = J-RJ45-HR911130C: DSC1: RJ45 内置千兆变压器带灯; DSC3: 90度插件; DSC4: HR911130C(汉仁); ID: 5; Part Name: RJ45; Part Number: J120103060005
L32 = L-IND: DSC1: ±20%; DSC2: Isat=2.3A; DSC3: Irms=2.1A; DSC4: 85mΩ; DSC5: 2.5*2.0*1.2mm; DSC6: WPN252012H2R2MTY01(顺络); ID: 14; Manufacture: 顺络; Part Name: 功率电感; Part Number: C060202340014; Price: 0.23
R183-R190 = R-0402: DSC1: ±1%; DSC2: 1/16W; ID: 453; Part Name: 贴片电阻; Part Number: C011002080453; Price: 0.01
R191 R192 = R-0402: DSC1: ±1%; DSC2: 1/16W; ID: 708; Part Name: 贴片电阻; Part Number: C011002080708; Price: 0.01
R193 = R-0402: DSC1: ±1%; DSC2: 1/16W; ERP Number: 1010200450; ID: 630; Part Name: 贴片电阻; Part Number: C011002080630; Price: 0.01
R194 = R-0402: DSC1: ±1%; DSC2: 1/16W; ID: 638; Part Name: 贴片电阻; Part Number: C011002080638; Price: 0.01
R212 = R-0402: DSC1: ±1%; DSC2: 1/16W; ERP Number: 1010200324; ID: 785; Part Name: 贴片电阻; Part Number: C011002080785; Price: 0.01
U24 = Ethernet_RTL8211F: Integrated 10/100/1000 Gigabit Ethernet Transceiver，Supports IEEE 802.3az-2010,; Created by: JJJ; Manufacturer: RealTek(瑞昱); Part Type: Ethernet; Priority: A
XT4 = XTAL-4P: DSC1: 40Ω; DSC2: ±10ppm; DSC3: 12pF; DSC4: -40℃~+85℃; DSC5: 3.2*2.5mm 4P; ID: 6; Manufacture: 泰晶; Part Name: 贴片无源晶振; Part Number: C050102290006; Price: 0.48

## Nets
GND: C96.1 C107.1 C108.1 C110.1 C112.1 C113.1 C114.1 C115.1 C116.1 C117.1 C118.1 C119.1 C120.1 C121.1 C122.1 C123.1 C124.1 C125.1 C126.1 C127.1 C128.1 C129.1 C130.1 C131.1 C132.1 C133.1 C134.1 C135.1 C138.1 C139.1 C140.1 C142.1 C143.1 C144.1 C145.1 C146.1 C147.1 C148.1 C149.1 C150.1 C151.1 C152.1 C169.1 C170.1 C171.1 C172.1 C173.1 C174.1 C175.1 C176.1 C177.1 C178.1 C179.1 C180.1 C181.1 C182.1 C183.1 C184.1 C185.1 C186.1 C187.1 C188.1 C189.1 C190.1 C191.1 C270.1 C493.1 C496.1 D47.3 D47.8 D48.3 D48.8 D52.3 D52.8 D53.3 D53.8 D54.1(I/O2) D55.1(I/O2) D57.3 D57.8 D58.3 D58.8 D59.1(I/O2) D61.1(I/O2) D62.2(I/O1) D63.2(I/O1) D64.2(I/O1) D65.2(I/O1) D66.3 D66.8 D67.3 D67.8 D68.3 D68.8 D69.3 D69.8 D70.3 D70.8 D71.2 D72.2 D108.1(I/O2) D109.1(I/O2) D110.1(I/O2) D111.1(I/O2) J18.2 J18.5 J18.8 J18.11 J18.17 J18.20 J18.21 J18.22 J18.23 J19.4 J19.13 J19.14 J21.1 J21.2 J22.11 J22.16 J22.19 J22.22 J22.25 J22.28 J22.31 J22.34 J22.37 J22.41 J22.42 J23.11 J23.16 J23.19 J23.22 J23.25 J23.28 J23.31 J23.34 J23.37 J23.41 J23.42 J24.1 J24.7 J24.8 J26.5(3) J26.6(18) J26.13(7) J26.14(22) J26.25(13) J26.26(28) J27.1 J27.2 J28.10 J28.13 J28.16 J28.19 J28.22 J28.25 J28.26 J30.10(GND) Q7.2 Q10.2 R86.2 R105.2 R106.2 R107.2 R116.2 R117.2 R118.2 R121.1 R125.2 R192.2 R194.2 R195.1 R199.1 R203.1 R206.1 R208.1 R210.1 R212.1 R213.1 R216.1 R375.2 R387.1 R389.1 R391.1 U14.1(~{OE}) U14.3(GND) U15.2(GND) U16.2(GND) U17.5(GND) U17.9(TEST) U17.37(VSS_PLL) U17.49(EPAD) U18.1(~{OE}) U18.3(GND) U19.2(GND) U20.2(GND) U21.2(GND) U24.41(E_Pad) XT4.2 XT4.4 ; also on sheet 4 5 6 7 8 16 17 18 19 20 21 22 23
GND_EARTH: J30.SH1 J30.SH2 ; also on sheet 4 16
VCC1V5_DVP: C148.2 C149.2 C492.1 J28.3 R388.2 U20.5(OUT)
VCC1V8_DVP: C144.2 C145.2 J28.4 R148.1 R386.2 U19.5(OUT)
VCC2V8_DVP: C151.2 C152.2 J28.1 J28.2 R390.2 U21.5(OUT)
VCC3V3_PHY0: C187.2 C188.2 C189.2 C190.2 C191.2 R191.2 R196.2 R200.2 R218.1 R229.2 U24.11(AVDD33) U24.29(DVDD33) U24.40(AVDD33)
VCC5V0_SYS: C108.2 C113.2 C114.2 C121.2 C122.2 C139.2 J20.3 J25.3 L27.1 L28.1 Q8.1(GATE) Q17.1(GATE) R127.1 R380.1 U14.5(Vcc) U15.6(VIN) U16.6(VIN) U18.5(Vcc) ; also on sheet 4 5 7 8 20 22
VCC5V_HDMI_TX: C96.2 D51.C J18.18
VCC12V_DCIN: J20.1 J21.5 J21.6 J25.1 J27.5 J27.6 ; also on sheet 4
VCC_1V8: C132.2 L30.2 R146.2 R147.2 R221.1 ; also on sheet 5 16 21 23
VCC_EDP_OUT: C110.2 C111.2 J20.2 J20.4 J20.6 Q6.2(SOURCE) R90.1
VCC_EDP_OUT_: C112.2 J19.1 J19.2 Q6.3(DRAIN)
VCC_LEDA_TX0: C115.2 C116.2 D56.C J22.1 J22.2 U15.5(OVP)
VCC_LEDA_TX1: C119.2 C120.2 D60.C J23.1 J23.2 U16.5(OVP)
VCC_LEDK_TX0: J22.9 J22.10 R104.2 R106.1 R107.1
VCC_LEDK_TX1: J23.9 J23.10 R115.2 R117.1 R118.1
VCCIO_PHY0: C183.2 C184.2 C185.2 R220.2 R221.2 R222.2 U24.28(DVDD_RG)
VCCIO_PHY1: R207.2 R209.2 R211.2 R214.2 R217.2 ; also on sheet 16
VDD10_PHY0: C175.2 C176.2 C177.2 C178.2 C180.2 C181.2 L32.2 U24.3(AVDD10) U24.8(AVDD10) U24.21(DVDD10) U24.38(AVDD10)
VDD_3V3: C107.2 C117.2 C123.2 C124.2 C128.2 C143.2 C147.2 C150.2 J19.19 J20.5 J22.38 J22.39 J23.38 J23.39 J24.6 J25.5 L29.2 Q3.1(GATE) Q4.1(GATE) R81.1 R83.1 R87.1 R103.1 R109.2 R110.2 R119.1 R126.1 R149.1 R150.1 R151.1 R222.1 R229.1 R374.1 R378.1 U19.1(VIN) U20.1(VIN) U21.1(VIN) ; also on sheet 4 6 7 8 16 17 18 22 23
VDD_LVDS: C133.2 C134.2 C135.2 L30.1 U17.35(VDD_LVDS1) U17.36(VDD_PLL) U17.38(VDD_LVDS2)
VDD_USB_5V: D49.A D51.A Q5.1(GATE) ; also on sheet 4 7 19 21
CIF_CLKO_: C270.2 J28.9 R143.2
CIF_CLKOUT_SOC: R143.1 ; also on sheet 5
CIF_PDN0_: J28.6 R142.2
CIF_RST: C146.2 J28.5 R148.2 R377.2
CIF_RST_GPIO3_A3: R377.1 ; also on sheet 5
EDP_HPD: J19.20 R88.2
EDP_HPDIN_M1: R88.1 ; also on sheet 5
EDP_ON_: J21.4 Q17.2(SOURCE) R379.2 R380.2
EDP_PWM4: R89.1 R108.1 U14.2(A) ; also on sheet 5
EDP_PWM4_: J21.3 R89.2 U14.4(Y)
EDP_TX_AUXN: C99.2 ; also on sheet 5
EDP_TX_AUXN_: C99.1 J19.15 R374.2
EDP_TX_AUXP: C100.2 ; also on sheet 5
EDP_TX_AUXP_: C100.1 J19.16 R375.1
EDP_TX_D0N: C105.2 ; also on sheet 5
EDP_TX_D0N_: C105.1 J19.7
EDP_TX_D0P: C106.2 ; also on sheet 5
EDP_TX_D0P_: C106.1 J19.8
EDP_TX_D1N: C103.2 ; also on sheet 5
EDP_TX_D1N_: C103.1 J19.9
EDP_TX_D1P: C104.2 ; also on sheet 5
EDP_TX_D1P_: C104.1 J19.10
EDP_TX_D2N: C101.2 ; also on sheet 5
EDP_TX_D2N_: C101.1 J19.11
EDP_TX_D2P: C102.2 ; also on sheet 5
EDP_TX_D2P_: C102.1 J19.12
EDP_TX_D3N: C97.2 ; also on sheet 5
EDP_TX_D3N_: C97.1 J19.17
EDP_TX_D3P: C98.2 ; also on sheet 5
EDP_TX_D3P_: C98.1 J19.18
GM_VDDIO: C127.2 C130.2 C131.2 L29.1 R120.1 R122.1 U17.10(VDDIO) U17.13(PVDD2)
GMAC0_INT/PMEB_GPIO3_B0: R215.2 ; also on sheet 5
GMAC0_MCLKINOUT: C171.2 R193.1 R194.1 ; also on sheet 5
GMAC0_MDC: U24.13(MDC) ; also on sheet 5
GMAC0_MDIO: R220.1 U24.14(MDIO) ; also on sheet 5
GMAC0_RSTn_GPIO3_A5: R219.1 ; also on sheet 5
GMAC0_RXCLK: C186.2 R227.2 ; also on sheet 5
GMAC0_RXD0: R223.2 ; also on sheet 5
GMAC0_RXD1: R224.2 ; also on sheet 5
GMAC0_RXD2: R225.2 ; also on sheet 5
GMAC0_RXD3: R226.2 ; also on sheet 5
GMAC0_RXDV_CRS: R228.2 ; also on sheet 5
GMAC0_TXCLK: C493.2 R205.1 ; also on sheet 5
GMAC0_TXCLK_: C174.2 R205.2 U24.20(TXC)
GMAC0_TXD0: R197.1 ; also on sheet 5
GMAC0_TXD0_: R197.2 U24.18(TXD0)
GMAC0_TXD1: R198.1 ; also on sheet 5
GMAC0_TXD1_: R198.2 U24.17(TXD1)
GMAC0_TXD2: R201.1 ; also on sheet 5
GMAC0_TXD2_: R201.2 U24.16(TXD2)
GMAC0_TXD3: R202.1 ; also on sheet 5
GMAC0_TXD3_: R202.2 U24.15(TXD3)
GMAC0_TXEN: R204.1 ; also on sheet 5
GMAC0_TXEN_: R204.2 U24.19(TXCTL)
HDMI_TX_CEC_PORT: D108.2(I/O1) J18.13 Q5.3(DRAIN)
HDMI_TX_CLKN: L26.2 ; also on sheet 5
HDMI_TX_CLKN_: D48.5 D48.6 J18.12 L26.3
HDMI_TX_CLKP: L26.1 ; also on sheet 5
HDMI_TX_CLKP_: D48.4 D48.7 J18.10 L26.4
HDMI_TX_D0N: L25.2 ; also on sheet 5
HDMI_TX_D0N_: D48.2 D48.9 J18.9 L25.3
HDMI_TX_D0P: L25.1 ; also on sheet 5
HDMI_TX_D0P_: D48.1 D48.10 J18.7 L25.4
HDMI_TX_D1N: L24.2 ; also on sheet 5
HDMI_TX_D1N_: D47.5 D47.6 J18.6 L24.3
HDMI_TX_D1P: L24.1 ; also on sheet 5
HDMI_TX_D1P_: D47.4 D47.7 J18.4 L24.4
HDMI_TX_D2N: L23.2 ; also on sheet 5
HDMI_TX_D2N_: D47.2 D47.9 J18.3 L23.3
HDMI_TX_D2P: L23.1 ; also on sheet 5
HDMI_TX_D2P_: D47.1 D47.10 J18.1 L23.4
HDMI_TX_HPD_PORT: D111.2(I/O1) J18.19 R85.2 R86.1
HDMI_TX_HPDIN: R85.1 ; also on sheet 5
HDMI_TXDDC_SCL_PORT: D109.2(I/O1) J18.15 Q3.3(DRAIN) R82.2
HDMI_TXDDC_SDA_PORT: D110.2(I/O1) J18.16 Q4.3(DRAIN) R84.2
HDMITX_CEC_M0: Q5.2(SOURCE) R87.2 ; also on sheet 5
I2C3_SCL_M1: R109.1 R113.1 ; also on sheet 5
I2C3_SDA_M1: R110.1 R114.1 ; also on sheet 5
I2C4_SCL_M0: R144.1 R147.1 ; also on sheet 5
I2C4_SDA_M0: R145.1 R146.1 ; also on sheet 5
I2C5_SCL-HDMI: Q3.2(SOURCE) R81.2 ; also on sheet 5
I2C5_SDA-HDMI: Q4.2(SOURCE) R83.2 ; also on sheet 5
LAN0_A+: D72.6 J30.2(MDI_0+) R190.2
LAN0_A-: D72.1 J30.3(MDI_0-) R189.2
LAN0_B+: D72.3 J30.4(MDI_1+) R188.2
LAN0_B-: D72.4 J30.7(MDI_1-) R187.2
LAN0_C+: D71.6 J30.5(MDI_2+) R186.2
LAN0_C-: D71.1 J30.6(MDI_2-) R185.2
LAN0_D+: D71.3 J30.8(MDI_3+) R184.2
LAN0_D-: D71.4 J30.9(MDI_3-) R183.2
LCM_VIO_EN: Q7.1 Q10.1 ; also on sheet 17
LVDS0_CLKN: D68.5 D68.6 J26.15(8) U17.27(A_CLKN)
LVDS0_CLKP: D68.4 D68.7 J26.16(23) U17.28(A_CLKP)
LVDS0_D0N: D66.2 D66.9 J26.7(4) U17.33(A_Y0N)
LVDS0_D0P: D66.1 D66.10 J26.8(19) U17.34(A_Y0P)
LVDS0_D1N: D66.5 D66.6 J26.9(5) U17.31(A_Y1N)
LVDS0_D1P: D66.4 D66.7 J26.10(20) U17.32(A_Y1P)
LVDS0_D2N: D68.2 D68.9 J26.11(6) U17.29(A_Y2N)
LVDS0_D2P: D68.1 D68.10 J26.12(21) U17.30(A_Y2P)
LVDS0_D3N: D69.2 D69.9 J26.17(9) U17.25(A_Y3N)
LVDS0_D3P: D69.1 D69.10 J26.18(24) U17.26(A_Y3P)
LVDS1_CLKN: D70.2 D70.9 J26.27(14) U17.41(B_CLKN)
LVDS1_CLKP: D70.1 D70.10 J26.28(29) U17.42(B_CLKP)
LVDS1_D0N: D69.5 D69.6 J26.19(10) U17.47(B_Y0N)
LVDS1_D0P: D69.4 D69.7 J26.20(25) U17.48(B_Y0P)
LVDS1_D1N: D67.2 D67.9 J26.21(11) U17.45(B_Y1N)
LVDS1_D1P: D67.1 D67.10 J26.22(26) U17.46(B_Y1P)
LVDS1_D2N: D67.5 D67.6 J26.23(12) U17.43(B_Y2N)
LVDS1_D2P: D67.4 D67.7 J26.24(27) U17.44(B_Y2P)
LVDS1_D3N: D70.5 D70.6 J26.29(15) U17.39(B_Y3N)
LVDS1_D3P: D70.4 D70.7 J26.30 U17.40(B_Y3P)
LVDS_ON_: J27.4 Q8.2(SOURCE) R127.2 R128.2
LVDS_PWM5: R102.1 R130.1 U18.2(A) ; also on sheet 5
LVDS_PWM5_: J27.3 R130.2 U18.4(Y)
LVDS_VIO: C138.2 C140.2 C141.2 J25.2 J25.4 J25.6 Q9.2(SOURCE) R129.1
LVDS_VIO_: C142.2 J26.1 J26.2(16) J26.3(2) Q9.3(DRAIN)
MIPI_CAM0_PDN_L_GPIO2_C1: R142.1 ; also on sheet 5
MIPI_CSI_CLKN: J28.17 R141.2
MIPI_CSI_CLKP: J28.18 R140.2
MIPI_CSI_D0N: J28.11 R133.2
MIPI_CSI_D0P: J28.12 R132.2
MIPI_CSI_D1N: J28.14 R135.2
MIPI_CSI_D1P: J28.15 R134.2
MIPI_CSI_D2N: J28.20 R137.2
MIPI_CSI_D2P: J28.21 R136.2
MIPI_CSI_D3N: J28.23 R139.2
MIPI_CSI_D3P: J28.24 R138.2
MIPI_CSI_RX_CLK0N: R141.1 ; also on sheet 5
MIPI_CSI_RX_CLK0P: R140.1 ; also on sheet 5
MIPI_CSI_RX_D0N: R133.1 ; also on sheet 5
MIPI_CSI_RX_D0P: R132.1 ; also on sheet 5
MIPI_CSI_RX_D1N: R135.1 ; also on sheet 5
MIPI_CSI_RX_D1P: R134.1 ; also on sheet 5
MIPI_CSI_RX_D2N: R137.1 ; also on sheet 5
MIPI_CSI_RX_D2P: R136.1 ; also on sheet 5
MIPI_CSI_RX_D3N: R139.1 ; also on sheet 5
MIPI_CSI_RX_D3P: R138.1 ; also on sheet 5
MIPI_DSI_TX0_CLKN: R98.1 U17.19(DACN) ; also on sheet 5
MIPI_DSI_TX0_CLKN_: D53.2 D53.9 J22.27 R98.2
MIPI_DSI_TX0_CLKP: R97.1 U17.18(DACP) ; also on sheet 5
MIPI_DSI_TX0_CLKP_: D53.1 D53.10 J22.26 R97.2
MIPI_DSI_TX0_D0N: R94.1 U17.15(DA0N) ; also on sheet 5
MIPI_DSI_TX0_D0N_: D55.2(I/O1) J22.33 R94.2
MIPI_DSI_TX0_D0P: R93.1 U17.14(DA0P) ; also on sheet 5
MIPI_DSI_TX0_D0P_: D54.2(I/O1) J22.32 R93.2
MIPI_DSI_TX0_D1N: R96.1 U17.17(DA1N) ; also on sheet 5
MIPI_DSI_TX0_D1N_: D53.5 D53.6 J22.30 R96.2
MIPI_DSI_TX0_D1P: R95.1 U17.16(DA1P) ; also on sheet 5
MIPI_DSI_TX0_D1P_: D53.4 D53.7 J22.29 R95.2
MIPI_DSI_TX0_D2N: R100.1 U17.21(DA2N) ; also on sheet 5
MIPI_DSI_TX0_D2N_: D52.5 D52.6 J22.24 R100.2
MIPI_DSI_TX0_D2P: R99.1 U17.20(DA2P) ; also on sheet 5
MIPI_DSI_TX0_D2P_: D52.4 D52.7 J22.23 R99.2
MIPI_DSI_TX0_D3N: R101.1 U17.23(DA3N) ; also on sheet 5
MIPI_DSI_TX0_D3N_: D52.2 D52.9 J22.21 R101.2
MIPI_DSI_TX0_D3P: R92.1 U17.22(DA3P) ; also on sheet 5
MIPI_DSI_TX0_D3P_: D52.1 D52.10 J22.20 R92.2
MIPI_DSI_TX0_RST: C118.2 J22.36 R103.2
MIPI_DSI_TX1_CLKN: D58.2 D58.9 J23.27 ; also on sheet 5
MIPI_DSI_TX1_CLKP: D58.1 D58.10 J23.26 ; also on sheet 5
MIPI_DSI_TX1_D0N: D61.2(I/O1) J23.33 ; also on sheet 5
MIPI_DSI_TX1_D0P: D59.2(I/O1) J23.32 ; also on sheet 5
MIPI_DSI_TX1_D1N: D58.5 D58.6 J23.30 ; also on sheet 5
MIPI_DSI_TX1_D1P: D58.4 D58.7 J23.29 ; also on sheet 5
MIPI_DSI_TX1_D2N: D57.5 D57.6 J23.24 ; also on sheet 5
MIPI_DSI_TX1_D2P: D57.4 D57.7 J23.23 ; also on sheet 5
MIPI_DSI_TX1_D3N: D57.2 D57.9 J23.21 ; also on sheet 5
MIPI_DSI_TX1_D3P: D57.1 D57.10 J23.20 ; also on sheet 5
MIPI_DSI_TX1_RST: C125.2 J23.36 R119.2
MIPI_TX0_BL_PWM5: R102.2 R105.1 U15.4(EN)
MIPI_TX1_BL_PWM4: R108.2 R116.1 U16.4(EN)
PCA9539_IO1_3: Q8.3(DRAIN) R126.2 R128.1 ; also on sheet 17
PCA9539_IO1_6: Q17.3(DRAIN) R378.2 R379.1 ; also on sheet 17
PHY0_CLKOUT125: R193.2 U24.35(CLKOUT)
PHY0_G_LED-: J30.12(G_LED-) R192.1
PHY0_LED0/CFG_EXT: R195.2 R196.1 U24.32(LED0/CFG_EXT)
PHY0_LED1/CFG_LDO0: C173.2 J30.11(G_LED+) R203.2 U24.33(LED1/CFG_LDO0)
PHY0_LED2/CFG_LDO1: C172.2 J30.13(Y_LED-) R199.2 R200.1 U24.34(LED2/CFG_LDO1)
PHY0_MDI0+: R190.1 U24.1(MDI[0]+)
PHY0_MDI0-: R189.1 U24.2(MDI[0]-)
PHY0_MDI1+: R188.1 U24.4(MDI[1]+)
PHY0_MDI1-: R187.1 U24.5(MDI[1]-)
PHY0_MDI2+: R186.1 U24.6(MDI[2]+)
PHY0_MDI2-: R185.1 U24.7(MDI[2]-)
PHY0_MDI3+: R184.1 U24.9(MDI[3]+)
PHY0_MDI3-: R183.1 U24.10(MDI[3]-)
PHY0_REG_OUT: L32.1 U24.30(REG_OUT)
PHY0_RSTn: C182.2 R218.2 R219.2 U24.12(PHYRSTB)
PHY0_RXCLK/PHYAD1: C496.2 R208.2 R209.1 R227.1 U24.27(RXC/PHYAD1)
PHY0_RXD0/RXDLY: R210.2 R211.1 R223.1 U24.25(RXD0/RXDLY)
PHY0_RXD1/TXDLY: R213.2 R214.1 R224.1 U24.24(RXD1/TXDLY)
PHY0_RXD2/PLLOFF: R216.2 R217.1 R225.1 U24.23(RXD2/PLLOFF)
PHY0_RXD3/PHYAD0: R207.1 R226.1 U24.22(RXD3/PHYAD0)
PHY0_RXDV/PHYAD2: R206.2 R228.1 U24.26(RXCTL/PHYAD2)
PHY0_XTALIN: C169.2 U24.36(XTAL_IN) XT4.3
PHY0_XTALOUT: C170.2 U24.37(XTAL_OUT/EXT_CLK) XT4.1
PHY0_Y_LED+: J30.14(Y_LED+) R191.1
REFCLK_GM8775C: R125.1 U17.24(REFCLK)
RSET0: R212.2 U24.39(RSET)
SCL_CAM: J28.7 R144.2
SDA_CAM: J28.8 R145.2
TP_INT: D64.1(I/O2) J24.4 R112.2
TP_INT_L_GPIO3_B4: R112.1 ; also on sheet 5
TP_RST: D65.1(I/O2) J24.5 R111.2
TP_RST_L_GPIO3_B3: R111.1 ; also on sheet 5
TP_SCL: D63.1(I/O2) J24.3 R113.2
TP_SDA: D62.1(I/O2) J24.2 R114.2
N17846666: R215.1 U24.31(INTB/PMEB)
N67269040: D60.A L28.2 U16.1(LX)
N68120764: D49.C R82.1 R84.1
N68141872: R115.1 U16.3(FB)
N68550545: C126.2 C129.2 U17.11(VCORE)
N68551303: R121.2 U17.8(I2C_TYPE)
N68551306: R122.2 U17.12(EN)
N68551396: R120.2 U17.7(I2C_ADDR)
N68552374: C141.1 Q9.1(GATE) R129.2 R131.2
N68552446: Q10.3 R131.1
N68558276: R104.1 U15.3(FB)
N68558638: D56.A L27.2 U15.1(LX)
N68582360: C111.1 Q6.1(GATE) R90.2 R91.2
N68582430: Q7.3 R91.1
N68782340: R149.2 U19.3(EN)
N68782427: R150.2 U20.3(EN)
N68782451: R151.2 U21.3(EN)
N68888039: C179.2 J30.1(CT1/2/3/4)
N69206132: R386.1 R389.2 U19.4(NC)
N69206262: C492.2 R387.2 R388.1 U20.4(NC)
N69206971: R390.1 R391.2 U21.4(NC)

Not connected (* = marked no-connect by the designer): D71 5*; D72 5*; J18 14*; J19 3 5 6; J22 3 4 5 6 7 8 12 13 14 15 17 18 35 40; J23 3 4 5 6 7 8 12 13 14 15 17 18 35 40; J26 4(17); U17 1(SCL) 2(SDA)* 3(GPIO0) 4(GPIO1) 6(IRQ)

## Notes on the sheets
sheet 9
- HDMI A Type Port
- HDMI TX DDC
- HDMI TX HPD
- HDMI TX CEC
- Note:Option for CEC support.
sheet 10
- eDP_TX
- Backlight Power
sheet 11
- MIPI_DSI_TX0
sheet 12
- MIPI_DSI_TX1
sheet 13
- MIPI_DSI_TX0
- LVDS
sheet 14
- 1.2V 时
  R387 = 200K
  C492应上件
sheet 15
- Giga PHY1
- RGMII Power Source
- CFG_EXT
- CFG_LDO[1:0]
- External 3.3V
- 1'b1
- 2'b00
- External 1.8V
- 1'b1
- 2'b10
- Internal 1.8V (default)
- 1'b0
- 2'b10
- 3.3Vpp
- MAC <----- PHY
- Reserve for EMI.
- Reserve for EMI.
- VCC_PHY0_IO Voltage Config
- Close to SOC
- PHY Address Config
- PHY Address
- PHYAD[2:0]
- 1 (default)
- 3'b001
- Pull-up for additional 2ns delay to RXC for data latching
- Pull-up for additional 2ns delay to TXC for data latching
- Pull-up to disable PLL @ ALDPS mode(Low power mode)
- Close to PIN21
- Close to PIN30
- RTL8211F-CG(SW Mode)
- RTL8211FI-CG(SW Mode)Industrial
- Close to PIN3,8,38
- RTL8211F-CG(SW Mode)
- RTL8211FI-CG(SW Mode)Industrial
- Note:
- According to the actual
  choice of mounted
  Cannot be mounted
  at the same time
- PHYRSTB is 3.3V IO
- Close to PIN28
- Close to PIN11,40
- Close to PHY
- Close to PIN29
